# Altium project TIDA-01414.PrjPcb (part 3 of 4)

## Sheet TIDA-01414_SubWooferChannel.SchDoc: Main Schematic
size 431 x 279 mm; Date: Not shown in title block; ApprovedBy: Not shown in title block; CheckedBy: Not shown in title block; Author: Not shown in title block; CompanyName: Not shown in title block; DrawnBy: LDN; Engineer: Not shown in title block; Organization: Not shown in title block; Address1: Not shown in title block; Address2: Not shown in title block; Address3: Not shown in title block; Address4: Not shown in title block; DocumentNumber: 8; Revision: Use project parameter SCH_Rev; SheetNumber: 8; SheetTotal: 12; PageSetup: Record=PageOptions¦CenterHorizontal=True¦CenterVertical=True¦PrintScale=1.00¦XCorrection=1.00¦YCorrection=1.00¦PrintKind=0¦BorderSize=5000000¦LeftOffset=0¦BottomOffset=0¦Orientation=2¦PaperLength=1000¦PaperWidth=1000¦Scale=100¦PaperSource=15¦PrintQuality=600¦MediaType=1¦DitherType=10¦PaperKind=Letter¦PrintScaleMode=1
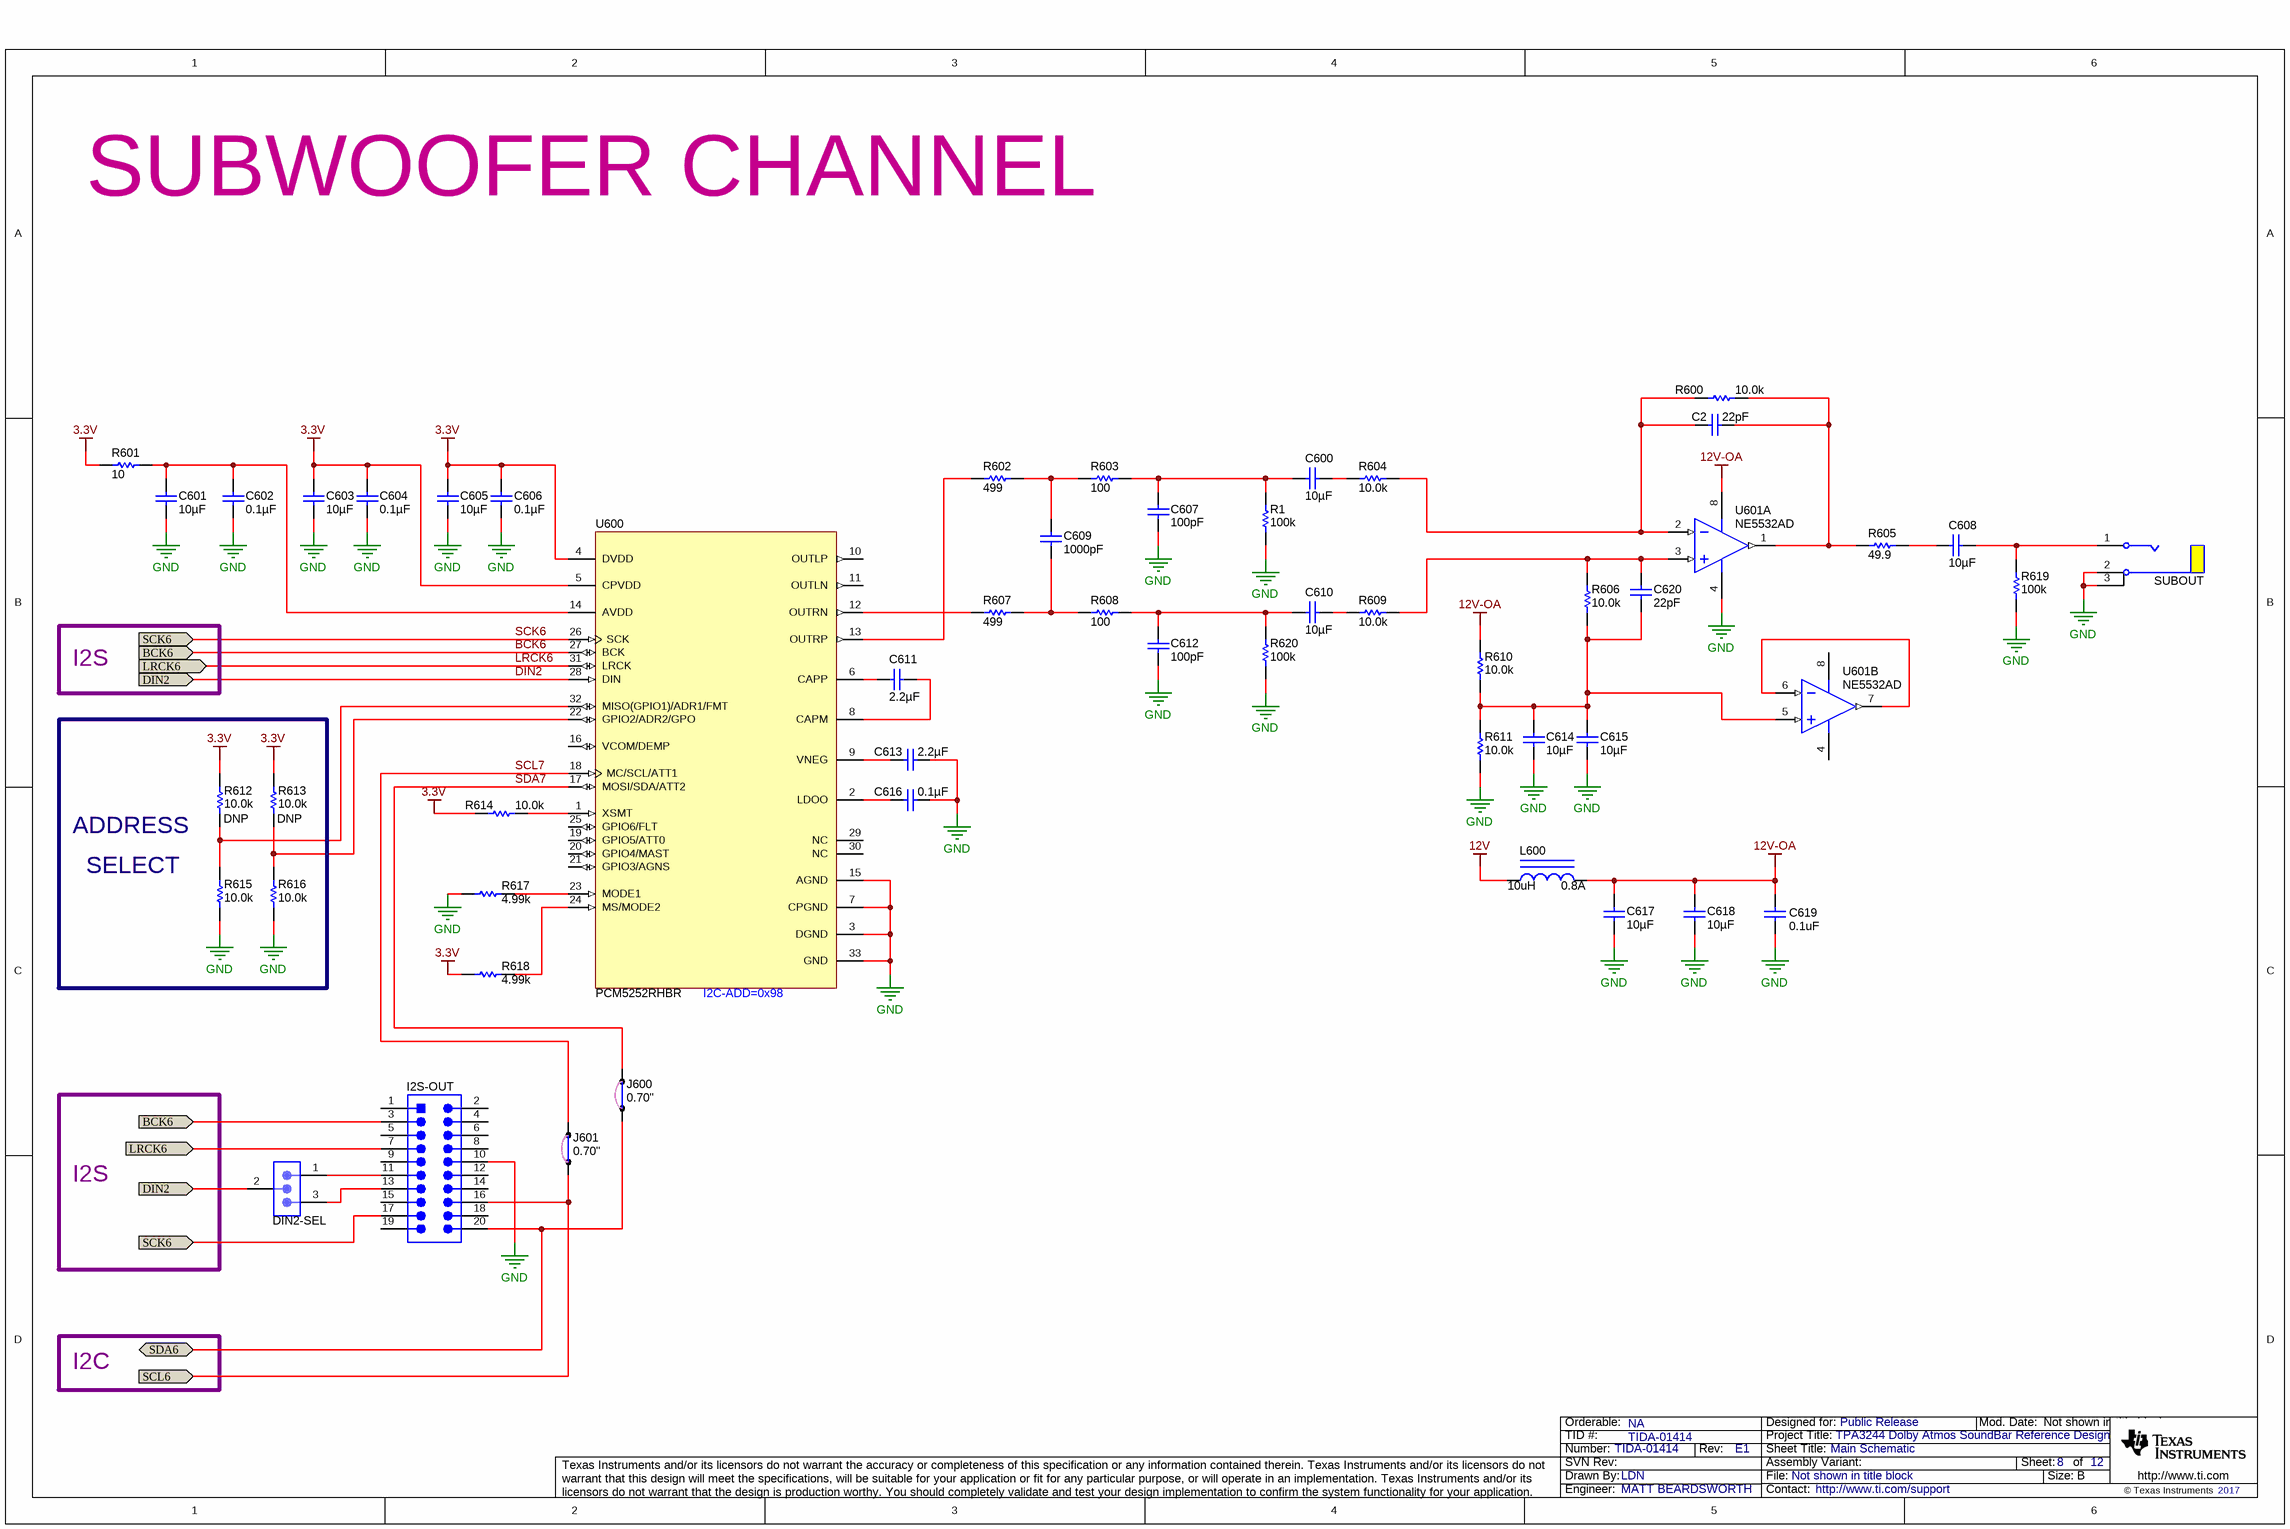
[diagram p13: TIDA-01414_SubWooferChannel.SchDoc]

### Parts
C2  ValueDisplayed: 22pF  [0603L]  (hidden comment: GRM1885C1H220JA01D)
C600  ValueDisplayed: 10µF  [1206_180]  (hidden comment: GRM31CR71C106KAC7L)
C601  ValueDisplayed: 10µF  [0603L]  (hidden comment: GRM188R61A106ME69D)
C602  ValueDisplayed: 0.1µF  [0402L]  (hidden comment: GRM155R71A104KA01D)
C603  ValueDisplayed: 10µF  [0603L]  (hidden comment: GRM188R61A106ME69D)
C604  ValueDisplayed: 0.1µF  [0402L]  (hidden comment: GRM155R71A104KA01D)
C605  ValueDisplayed: 10µF  [0603L]  (hidden comment: GRM188R61A106ME69D)
C606  ValueDisplayed: 0.1µF  [0402L]  (hidden comment: GRM155R71A104KA01D)
C607  ValueDisplayed: 100pF  [0603L]  (hidden comment: GRM1885C1H101JA01D)
C608  ValueDisplayed: 10µF  [0603L]  (hidden comment: GRM188R61C106MAALD)
C609  ValueDisplayed: 1000pF  [0402L]  (hidden comment: GRM1555C1H102JA01D)
C610  ValueDisplayed: 10µF  [1206_180]  (hidden comment: GRM31CR71C106KAC7L)
C611  ValueDisplayed: 2.2µF  [0402L]  (hidden comment: C1005X5R1A225K050BC)
C612  ValueDisplayed: 100pF  [0603L]  (hidden comment: GRM1885C1H101JA01D)
C613  ValueDisplayed: 2.2µF  [0402L]  (hidden comment: C1005X5R1A225K050BC)
C614  ValueDisplayed: 10µF  [0603L]  (hidden comment: GRM188R61C106MAALD)
C615  ValueDisplayed: 10µF  [0603L]  (hidden comment: GRM188R61C106MAALD)
C616  ValueDisplayed: 0.1µF  [0402L]  (hidden comment: GRM155R71A104KA01D)
C617  ValueDisplayed: 10µF  [0805_KTR]  (hidden comment: EMK212BJ106KG-T)
C618  ValueDisplayed: 10µF  [0805_KTR]  (hidden comment: EMK212BJ106KG-T)
C619  value 0.1uF  [0603L]  (hidden comment: C0603C104K5RACTU)
C620  ValueDisplayed: 22pF  [0603L]  (hidden comment: GRM1885C1H220JA01D)
DIN2-SEL  (no value)  [PBC03SAAN]
I2S-OUT  SBH11-PBPC-D10-ST-BK  [Sullins_SBH11-xxxC-D10-ST]  (value not drawn)
J600  0.70"  [CONN_923345-07-C]
J601  0.70"  [CONN_923345-07-C]
L600  value 10uH  Value2: 0.8A  [NRS4012]  (hidden comment: NRS4012T100MDGJV)
R1  value 100k  [0402L]  (hidden comment: CRCW0402100KFKED)
R600  ValueDisplayed: 10.0k  [0402L]  (hidden comment: ERJ-2RKF1002X)
R601  ValueDisplayed: 10  [0603L]  (hidden comment: CRCW060310R0JNEA)
R602  ValueDisplayed: 499  [0603L]  (hidden comment: CRCW0603499RFKEA)
R603  ValueDisplayed: 100  [0603L]  (hidden comment: CRCW0603100RFKEA)
R604  ValueDisplayed: 10.0k  [0402L]  (hidden comment: ERJ-2RKF1002X)
R605  ValueDisplayed: 49.9  [0603L]  (hidden comment: CRCW060349R9FKEA)
R606  ValueDisplayed: 10.0k  [0402L]  (hidden comment: ERJ-2RKF1002X)
R607  ValueDisplayed: 499  [0603L]  (hidden comment: CRCW0603499RFKEA)
R608  ValueDisplayed: 100  [0603L]  (hidden comment: CRCW0603100RFKEA)
R609  ValueDisplayed: 10.0k  [0402L]  (hidden comment: ERJ-2RKF1002X)
R610  ValueDisplayed: 10.0k  [0402L]  (hidden comment: ERJ-2RKF1002X)
R611  ValueDisplayed: 10.0k  [0402L]  (hidden comment: ERJ-2RKF1002X)
R612  DNP  ValueDisplayed: 10.0k  [0402L]
R613  DNP  ValueDisplayed: 10.0k  [0402L]
R614  ValueDisplayed: 10.0k  [0402L]  (hidden comment: ERJ-2RKF1002X)
R615  ValueDisplayed: 10.0k  [0402L]  (hidden comment: ERJ-2RKF1002X)
R616  ValueDisplayed: 10.0k  [0402L]  (hidden comment: ERJ-2RKF1002X)
R617  ValueDisplayed: 4.99k  [0402L]  (hidden comment: CRCW04024K99FKED)
R618  ValueDisplayed: 4.99k  [0402L]  (hidden comment: CRCW04024K99FKED)
R619  value 100k  [0402L]  (hidden comment: CRCW0402100KFKED)
R620  value 100k  [0402L]  (hidden comment: CRCW0402100KFKED)
SUBOUT  RCJ-024  [CONN_RCJ-024]  (value not drawn)
U600  PCM5252RHBR  [RHB0032E]
U601  NE5532AD  [D0008A_N]  (parts A,B of 2)

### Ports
BCK6 (in), DIN2 (in), LRCK6 (in), SCK6 (in), SCL6 (in), SDA6 (bidir)

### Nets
3.3V: C603.1 C604.1 C605.1 C606.1 R601.1 R612.2 R613.2 R614.1 R618.2 U600.4(DVDD) U600.5(CPVDD)
12V: L600.1
12V-OA: C617.1 C618.1 C619.1 L600.2 R610.1 U601.8(VCC+)
GND: C601.2 C602.2 C603.2 C604.2 C605.2 C606.2 C607.2 C612.2 C613.2 C614.1 C615.1 C616.2 C617.2 C618.2 C619.2 I2S-OUT.10 R1.1 R611.2 R615.1 R616.1 R617.2 R619.1 R620.1 SUBOUT.2 SUBOUT.3(R) U600.3(DGND) U600.7(CPGND) U600.15(AGND) U600.33(GND) U601.4(VCC-)
BCK6: I2S-OUT.3 U600.27(BCK) ; port BCK6
DIN2: DIN2-SEL.2 U600.28(DIN) ; port DIN2
LRCK6: I2S-OUT.7 U600.31(LRCK) ; port LRCK6
SCK6: I2S-OUT.17 U600.26(SCK) ; port SCK6
SCL6: I2S-OUT.16 J601.1 ; port SCL6
SCL7: J601.2 U600.18(MC/SCL/ATT1)
SDA6: I2S-OUT.20 J600.1 ; port SDA6
SDA7: J600.2 U600.17(MOSI/SDA/ATT2)
NetC2_1: C2.1 R600.2 R604.1 U601.2(IN1-)
NetC2_2: C2.2 R600.1 R605.1 U601.1(OUT1)
NetC600_1: C600.1 C607.1 R1.2 R603.2
NetC600_2: C600.2 R604.2
NetC601_1: C601.1 C602.1 R601.2 U600.14(AVDD)
NetC608_1: C608.1 R619.2 SUBOUT.1
NetC608_2: C608.2 R605.2
NetC609_1: C609.1 R602.2 R603.1
NetC609_2: C609.2 R607.2 R608.1
NetC610_1: C610.1 C612.1 R608.2 R620.2
NetC610_2: C610.2 R609.2
NetC611_1: C611.1 U600.6(CAPP)
NetC611_2: C611.2 U600.8(CAPM)
NetC613_1: C613.1 U600.9(VNEG)
NetC614_2: C614.2 C615.2 C620.1 R606.2 R610.2 R611.1 U601.5(IN2+)
NetC616_1: C616.1 U600.2(LDOO)
NetC620_2: C620.2 R606.1 R609.1 U601.3(IN1+)
NetDIN2-SEL_1: DIN2-SEL.1 I2S-OUT.11
NetDIN2-SEL_3: DIN2-SEL.3 I2S-OUT.13
NetR602_1: R602.1 U600.13(OUTRP)
NetR607_1: R607.1 U600.12(OUTRN)
NetR612_1: R612.1 R615.2 U600.32(MISO(GPIO1)/ADR1/FMT)
NetR613_1: R613.1 R616.2 U600.22(GPIO2/ADR2/GPO)
NetR614_2: R614.2 U600.1(XSMT)
NetR617_1: R617.1 U600.23(MODE1)
NetR618_1: R618.1 U600.24(MS/MODE2)
NetU601_6: U601.6(IN2-) U601.7(OUT2)

Not connected (* = marked no-connect by the designer): I2S-OUT 1 2 4 5 6 8 9 12 14 15 18 19; U600 10(OUTLP) 11(OUTLN) 16(VCOM/DEMP) 19(GPIO5/ATT0) 20(GPIO4/MAST) 21(GPIO3/AGNS) 25(GPIO6/FLT) 29(NC) 30(NC)

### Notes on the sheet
- SUBWOOFER CHANNEL
- I2S
- ADDRESS
- SELECT
- (near U600) I2C-ADD=0x98
- I2C

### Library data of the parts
C2 C620 = GRM1885C1H220JA01D: CAP, CERM, 22 pF, 50 V, +/- 5%, C0G/NP0, 0603; Manufacturer: MuRata; Polarized: N; CompType: Capacitor; Value: 22pF; U/M: EA; Cap_F: 0.000000000022; Tolerance_%: 5; Value1: Unknown; VDC_V: 50; Value2: 50V; TaMin_C: -55; TaMax_C: 125; Cap_Case: 0603; AEC Category: Q200; SizeArea_mm2: 1.28; SizeAreaWB_mm2: 4.68; SizeX_mm: 1.6; SizeY_mm: 0.8; SizeZ_mm: 1
C600 C610 = GRM31CR71C106KAC7L: CAP, CERM, 10 µF, 16 V, +/- 10%, X7R, 1206; Manufacturer: MuRata; Polarized: N; CompType: Capacitor; Value: 10uF; U/M: EA; Cap_F: 0.00001; Tolerance_%: 10; Value1: Unknown; VDC_V: 16; Value2: 16V; TaMin_C: -55; TaMax_C: 125; Cap_Case: 1206; AEC Category: Q200; SizeArea_mm2: 5.12; SizeAreaWB_mm2: 10.92; SizeX_mm: 3.2; SizeY_mm: 1.6; SizeZ_mm: 1.8
C601 C603 C605 = GRM188R61A106ME69D: CAP, CERM, 10 µF, 10 V, +/- 20%, X5R, 0603; Manufacturer: MuRata; Polarized: N; CompType: Capacitor; Value: 10uF; U/M: EA; Cap_F: 0.00001; Tolerance_%: 20; Value1: Unknown; VDC_V: 10; Value2: 10V; TaMin_C: -55; TaMax_C: 85; Cap_Case: 0603; AEC Category: Q200
C602 C604 C606 C616 = GRM155R71A104KA01D: CAP, CERM, 0.1 µF, 10 V, +/- 10%, X7R, 0402; Manufacturer: MuRata; Polarized: N; CompType: Capacitor; Value: 0.1uF; U/M: EA; Cap_F: 0.0000001; Tolerance_%: 10; Value1: Unknown; Value2: 10V; TaMin_C: -55; TaMax_C: 125; Cap_Case: 0402; AEC Category: Q200
C607 C612 = GRM1885C1H101JA01D: CAP, CERM, 100 pF, 50 V, +/- 5%, C0G/NP0, 0603; Manufacturer: MuRata; Polarized: N; CompType: Capacitor; Value: 100pF; U/M: EA; Cap_F: 0.0000000001; Tolerance_%: 5; Value1: Unknown; VDC_V: 50; Value2: 50V; TaMin_C: -55; TaMax_C: 125; Cap_Case: 0603; AEC Category: Q200
C608 C614 C615 = GRM188R61C106MAALD: CAP, CERM, 10 µF, 16 V, +/- 20%, X5R, 0603; Manufacturer: MuRata; Polarized: N; CompType: Capacitor; Value: 10uF; U/M: EA; Cap_F: 0.00001; Tolerance_%: 20; Value1: Unknown; VDC_V: 16; Value2: 16V; TaMin_C: -55; TaMax_C: 85; Cap_Case: 0603; AEC Category: Q200; SizeArea_mm2: 1.28; SizeAreaWB_mm2: 4.68; SizeX_mm: 1.6; SizeY_mm: 0.8; SizeZ_mm: 1
C609 = GRM1555C1H102JA01D: CAP, CERM, 1000 pF, 50 V, +/- 5%, C0G/NP0, 0402; Manufacturer: MuRata; Polarized: N; CompType: Capacitor; Value: 1000pF; U/M: EA; Cap_F: 0.000000001; Tolerance_%: 5; Value1: Unknown; VDC_V: 50; Value2: 50V; TaMin_C: -55; TaMax_C: 125; Cap_Case: 0402; AEC Category: Q200
C611 C613 = C1005X5R1A225K050BC: CAP, CERM, 2.2 µF, 10 V, +/- 10%, X5R, 0402; Manufacturer: TDK; Polarized: N; CompType: Capacitor; Value: 2.2uF; U/M: EA; Cap_F: 0.0000022; Tolerance_%: 10; Value1: Unknown; Value2: 10V; TaMin_C: -55; TaMax_C: 85; Cap_Case: 0402; AEC Category: Q200
C617 C618 = EMK212BJ106KG-T: CAP, CERM, 10 µF, 16 V, +/- 10%, X5R, 0805; Manufacturer: Taiyo Yuden; Polarized: N; CompType: Capacitor; Value: 10uF; U/M: EA; Cap_F: 0.00001; Tolerance_%: 10; Value1: Unknown; VDC_V: 16; Value2: 16V; TaMin_C: -55; TaMax_C: 85; Cap_Case: 0805; AEC Category: Q200
C619 = C0603C104K5RACTU: CAP, CERM, 0.1 µF, 50 V, +/- 10%, X7R, 0603; Manufacturer: Kemet; Polarized: N; CompType: Capacitor; ValueDisplayed: 0.1µF; U/M: EA; Cap_F: 0.0000001; Tolerance_%: 10; Value1: Unknown; VDC_V: 50; Value2: 50V; TaMin_C: -55; TaMax_C: 125; Cap_Case: 0603; AEC Category: Q200
DIN2-SEL = SIP3-90_PBC03SAAN: Header, 100mil, 3x1, Gold, TH; Manufacturer: Sullins Connector Solutions; Value: 1x3; U/M: EA
I2S-OUT = SBH11-PBPC-D10-ST-BK: Header (Shrouded), 2.54mm, 10x2, Gold, Black, TH; Manufacturer: Sullins Connector Solutions; SymbolCreator: a0412235; Pitch_mm: 2.54; Gender: Male; Shrouded: Y; Row_Count: 2; Current_A: 3; Voltage_V: 1000
J600 J601 = 923345-07-C: Jumper Wire, 700mil spacing, Violet, pkg of 150, TH; Manufacturer: 3M; SymbolCreator: a0412235
L600 = NRS4012T100MDGJV: Inductor, Wirewound, 10 µH, 0.8 A, 0.204 ohm, SMD; Manufacturer: Taiyo Yuden; ValueDisplayed: 10µH; Ind_H: 10.0E-6; Imax_A: 0.8; Irms: 1.1A @ 40C rise; Isat: 0.8A @ 30% inductance drop; DCR_ohm: 0.204; AEC Category: Q200
R1 R619 R620 = CRCW0402100KFKED: RES, 100 k, 1%, 0.063 W, 0402; Manufacturer: Vishay-Dale; CompType: Resistor; Res_ohm: 100000; Tolerance_%: 1; Power_W: 0.063; Value2: 0.063W; VDC_V: 50; TempCo: 100 ppm/C; EIA_Code: E96; U/M: EA; AEC Category: Q200
R600 R604 R606 R609-R616 = ERJ-2RKF1002X: RES, 10.0 k, 1%, 0.1 W, 0402; Manufacturer: Panasonic; CompType: Resistor; Value: 10.0k; Res_ohm: 10000; Value_Code: 10k0; Tolerance_%: 1; Power_W: 0.1; Value2: 0.1W; VDC_V: 50; TempCo: 100 ppm/C; EIA_Code: E96; U/M: EA; AEC Category: Q200
R601 = CRCW060310R0JNEA: RES, 10, 5%, 0.1 W, 0603; Manufacturer: Vishay-Dale; CompType: Resistor; Value: 10; Value_Code: 10R0; Tolerance_%: 5; Power_W: 0.1; Value2: 0.1W; VDC_V: 75; TempCo: 200 ppm/C; EIA_Code: E24; U/M: EA; AEC Category: Q200
R602 R607 = CRCW0603499RFKEA: RES, 499, 1%, 0.1 W, 0603; Manufacturer: Vishay-Dale; CompType: Resistor; Value: 499; Value_Code: 499R; Tolerance_%: 1; Power_W: 0.1; Value2: 0.1W; VDC_V: 75; TempCo: 100 ppm/C; EIA_Code: E96; U/M: EA; AEC Category: Q200
R603 R608 = CRCW0603100RFKEA: RES, 100, 1%, 0.1 W, 0603; Manufacturer: Vishay-Dale; CompType: Resistor; Value: 100; Value_Code: 100R; Tolerance_%: 1; Power_W: 0.1; Value2: 0.1W; VDC_V: 75; TempCo: 100 ppm/C; EIA_Code: E96; U/M: EA; AEC Category: Q200
R605 = CRCW060349R9FKEA: RES, 49.9, 1%, 0.1 W, 0603; Manufacturer: Vishay-Dale; CompType: Resistor; Value: 49.9; Value_Code: 49R9; Tolerance_%: 1; Power_W: 0.1; Value2: 0.1W; VDC_V: 75; TempCo: 100 ppm/C; EIA_Code: E96; U/M: EA; AEC Category: Q200; SizeArea_mm2: 1.28; SizeX_mm: 1.6; SizeY_mm: 0.8
R617 R618 = CRCW04024K99FKED: RES, 4.99 k, 1%, 0.063 W, 0402; Manufacturer: Vishay-Dale; CompType: Resistor; Value: 4.99k; Res_ohm: 4990; Value_Code: 4k99; Tolerance_%: 1; Power_W: 0.063; Value2: 0.063W; VDC_V: 50; TempCo: 100 ppm/C; EIA_Code: E96; U/M: EA; AEC Category: Q200
SUBOUT = RCJ-024: RCA Jack, Vertical, Yellow, TH; Manufacturer: CUI Inc.; SymbolCreator: Altium; Gender: Female; ContactFinish: Tin; Voltage_V: 500
U600 = PCM5252RHBR: 4.2VRMS DirectPath™, 114dB Audio Stereo Differential-Output DAC with 32-bit, 384kHz PCM Interface, RHB0032E; Alternate PartNumber: PCM5252RHBT; Manufacturer: Texas Instruments; SymbolCreator: Altium; CompType: IC; U/M: EA
U601 = NE5532AD: Dual Low-Noise Operational Amplifier, 10 to 30 V, 0 to 70 degC, 8-pin SOIC (D0008A), Green (RoHS & no Sb/Br); Alternate Manufacturer: Texas Instruments; Alternate PartNumber: Equivalent; CMRR(Min)(dB): 70; GBW(Typ)(MHz): 10; IIB(Max)(pA): 800000; Iq per channel(Max)(mA): 4; Number of Channels: 2; Slew Rate(Typ)(V/us): 9; Sub Family: General Purpose Amplifier, High Supply Voltage Amplifier (>=30V), Low Noise Amp (<=10nV/rtHz); Total Supply Voltage(Max)(+5V is 5, +/-5V is 10): 30; Vn at 1kHz(Typ)(nV/rtHz): 5

## Sheet TIDA-01414_PowerSupplies.SchDoc: Hardware
size 323 x 209 mm; Date: Not shown in title block; ApprovedBy: Not shown in title block; CheckedBy: Not shown in title block; Author: Not shown in title block; CompanyName: Not shown in title block; DrawnBy: LDN; Engineer: Not shown in title block; Organization: Not shown in title block; Address1: Not shown in title block; Address2: Not shown in title block; Address3: Not shown in title block; Address4: Not shown in title block; DocumentNumber: 9; Revision: Use project parameter SCH_Rev; SheetNumber: 9; SheetTotal: 12; PageSetup: Record=PageOptions¦CenterHorizontal=True¦CenterVertical=True¦PrintScale=1.00¦XCorrection=1.00¦YCorrection=1.00¦PrintKind=0¦BorderSize=5000000¦LeftOffset=0¦BottomOffset=0¦Orientation=2¦PaperLength=1000¦PaperWidth=1000¦Scale=100¦PaperSource=15¦PrintQuality=600¦MediaType=1¦DitherType=10¦PaperKind=Letter¦PrintScaleMode=1
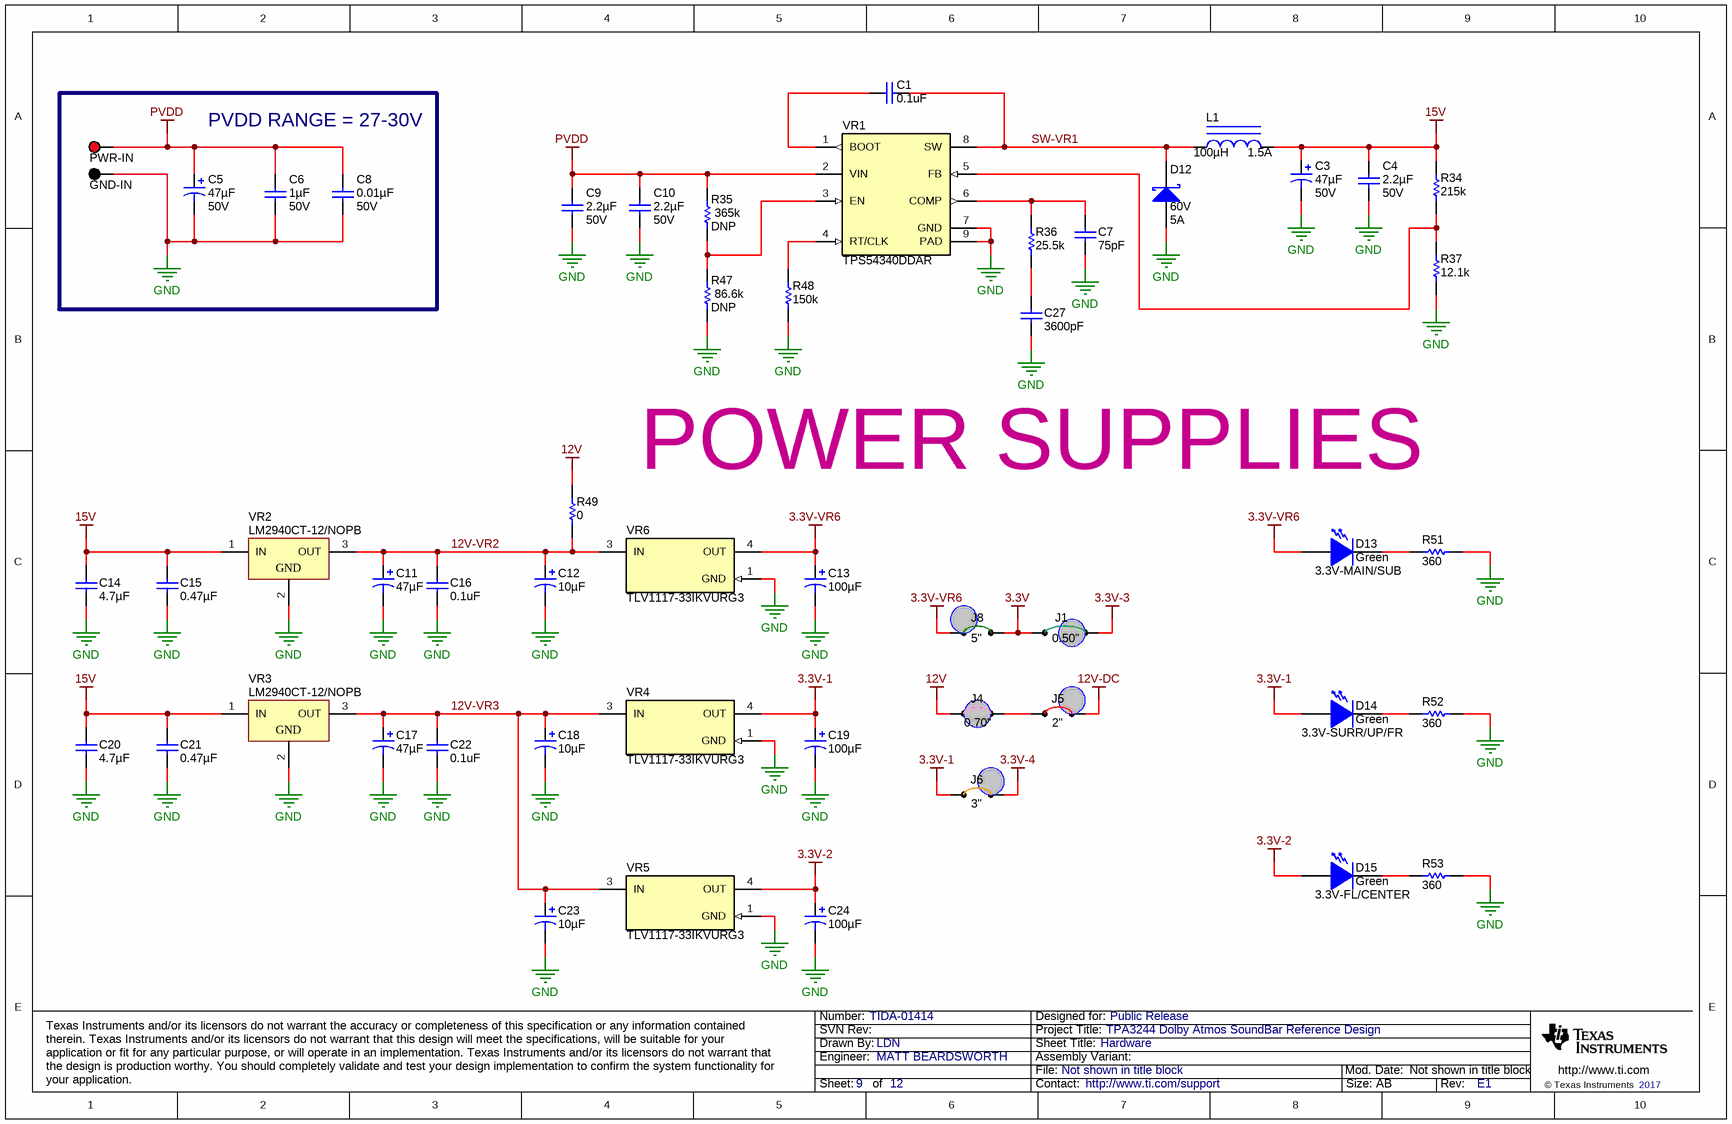
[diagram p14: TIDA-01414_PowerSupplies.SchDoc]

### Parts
C1  value 0.1uF  [0603L]  (hidden comment: C0603C104K5RACTU)
C3  ValueDisplayed: 47µF  Value2: 50V  [SM_RADIAL_E]  (hidden comment: +)
C4  ValueDisplayed: 2.2µF  Value2: 50V  [0805_KTR]  (hidden comment: C2012X7R1H225K125AC)
C5  ValueDisplayed: 47µF  Value2: 50V  [SM_RADIAL_E]  (hidden comment: +)
C6  ValueDisplayed: 1µF  Value2: 50V  [0603L]  (hidden comment: UMK107AB7105KA-T)
C7  ValueDisplayed: 75pF  [0603L]  (hidden comment: GRM1885C1H750JA01D)
C8  ValueDisplayed: 0.01µF  Value2: 50V  [0603L]  (hidden comment: C0603C103K5RACTU)
C9  ValueDisplayed: 2.2µF  Value2: 50V  [0805_KTR]  (hidden comment: C2012X7R1H225K125AC)
C10  ValueDisplayed: 2.2µF  Value2: 50V  [0805_KTR]  (hidden comment: C2012X7R1H225K125AC)
C11  ValueDisplayed: 47µF  [SM_RADIAL_D]  (hidden comment: +)
C12  ValueDisplayed: 10µF  [SM_RADIAL_B]  (hidden comment: +)
C13  ValueDisplayed: 100µF  [SM_RADIAL_C]  (hidden comment: +)
C14  ValueDisplayed: 4.7µF  [1206_180L]  (hidden comment: GRM31CR71E475KA88L)
C15  ValueDisplayed: 0.47µF  [0603L]  (hidden comment: GRM188R71E474KA12D)
C16  value 0.1uF  [0603L]  (hidden comment: C0603C104K5RACTU)
C17  ValueDisplayed: 47µF  [SM_RADIAL_D]  (hidden comment: +)
C18  ValueDisplayed: 10µF  [SM_RADIAL_B]  (hidden comment: +)
C19  ValueDisplayed: 100µF  [SM_RADIAL_C]  (hidden comment: +)
C20  ValueDisplayed: 4.7µF  [1206_180L]  (hidden comment: GRM31CR71E475KA88L)
C21  ValueDisplayed: 0.47µF  [0603L]  (hidden comment: GRM188R71E474KA12D)
C22  value 0.1uF  [0603L]  (hidden comment: C0603C104K5RACTU)
C23  ValueDisplayed: 10µF  [SM_RADIAL_B]  (hidden comment: +)
C24  ValueDisplayed: 100µF  [SM_RADIAL_C]  (hidden comment: +)
C27  ValueDisplayed: 3600pF  [0603L]  (hidden comment: GRM1885C1H362JA01D)
D12  value 60V  Value1: 5A  [SMC]  (hidden comment: B560C-13-F)
D13  3.3V-MAIN/SUB  value Green  [LED_LTST-C171]
D14  3.3V-SURR/UP/FR  value Green  [LED_LTST-C171]
D15  3.3V-FL/CENTER  value Green  [LED_LTST-C171]
GND-IN  DNP  [Keystone5001]  (value not drawn)
J1  0.50"  [WireJumper_923345-05-C]
J4  0.70"  [CONN_923345-07-C]
J5  2"  [3M_923345-20-C]
J6  3"  [3M_923345-30-C]
J8  5"  [3M_923345-50-C]
L1  ValueDisplayed: 100µH  Value2: 1.5A  [WE-PD_1050]  (hidden comment: 7447714101)
PWR-IN  DNP  [Keystone5000]  (value not drawn)
R34  ValueDisplayed: 215k  [0603L]  (hidden comment: CRCW0603215KFKEA)
R35  DNP  ValueDisplayed: 365k  [0603L]
R36  ValueDisplayed: 25.5k  [0603L]  (hidden comment: CRCW060325K5FKEA)
R37  ValueDisplayed: 12.1k  [0603L]  (hidden comment: CRCW060312K1FKEA)
R47  DNP  ValueDisplayed: 86.6k  [0603L]
R48  ValueDisplayed: 150k  [0603L]  (hidden comment: RC0603FR-07150KL)
R49  ValueDisplayed: 0  [1206L]  (hidden comment: CRCW12060000Z0EA)
R51  value 360  [0402L]  (hidden comment: CRCW0402360RJNED)
R52  value 360  [0402L]  (hidden comment: CRCW0402360RJNED)
R53  value 360  [0402L]  (hidden comment: CRCW0402360RJNED)
VR1  TPS54340DDAR  [DDA0008E_N]
VR2  LM2940CT-12/NOPB  [TO-220AB_Horizontal_100mil]
VR3  LM2940CT-12/NOPB  [TO-220AB_Horizontal_100mil]
VR4  TLV1117-33IKVURG3  [KVU0003A_N]
VR5  TLV1117-33IKVURG3  [KVU0003A_N]
VR6  TLV1117-33IKVURG3  [KVU0003A_N]

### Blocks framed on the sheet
PVDD RANGE = 27-30V: C5 C6 C8 GND-IN PWR-IN

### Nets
3.3V: J1.1 J8.1
3.3V-1: C19.1(+) D14.1(A) J6.1 VR4.4(OUT)
3.3V-2: C24.1(+) D15.1(A) VR5.4(OUT)
3.3V-3: J1.2
3.3V-4: J6.2
3.3V-VR6: C13.1(+) D13.1(A) J8.2 VR6.4(OUT)
12V: J4.1 R49.1
12V-DC: J5.2
15V: C3.1(+) C4.1 C14.1 C15.1 C20.1 C21.1 L1.2 R34.2 VR2.1(IN) VR3.1(IN)
GND: C3.2(-) C4.2 C5.2(-) C6.1 C7.2 C8.2 C9.2 C10.2 C11.2(-) C12.2(-) C13.2(-) C14.2 C15.2 C16.1 C17.2(-) C18.2(-) C19.2(-) C20.2 C21.2 C22.1 C23.2(-) C24.2(-) C27.2 D12.2(A) GND-IN.1 R37.1 R47.1 R48.1 R51.2 R52.2 R53.2 VR1.7(GND) VR1.9(PAD) VR2.2(GND) VR3.2(GND) VR4.1(GND) VR5.1(GND) VR6.1(GND)
PVDD: C5.1(+) C6.2 C8.1 C9.1 C10.1 PWR-IN.1 R35.2 VR1.2(VIN)
12V-VR2: C11.1(+) C12.1(+) C16.2 R49.2 VR2.3(OUT) VR6.3(IN)
12V-VR3: C17.1(+) C18.1(+) C22.2 C23.1(+) VR3.3(OUT) VR4.3(IN) VR5.3(IN)
SW-VR1: C1.2 D12.1(K) L1.1 VR1.8(SW)
NetC1_1: C1.1 VR1.1(BOOT)
NetC7_1: C7.1 R36.2 VR1.6(COMP)
NetC27_1: C27.1 R36.1
NetD13_2: D13.2(K) R51.1
NetD14_2: D14.2(K) R52.1
NetD15_2: D15.2(K) R53.1
NetJ4_2: J4.2 J5.1
NetR34_1: R34.1 R37.2 VR1.5(FB)
NetR35_1: R35.1 R47.2 VR1.3(EN)
NetR48_2: R48.2 VR1.4(RT/CLK)

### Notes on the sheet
- POWER SUPPLIES

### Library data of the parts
C1 C16 C22 = C0603C104K5RACTU: as C619 on sheet TIDA-01414_SubWooferChannel
C3 C5 = EEE-FK1H470P: CAP, AL, 47 µF, 50 V, +/- 20%, 0.68 ohm, SMD; Manufacturer: Panasonic; Polarized: Y; CompType: Capacitor; Value: 47uF; U/M: EA; Cap_F: 0.000047; Tolerance_%: 20; VDC_V: 50; ESR_ohm: 0.68; IRMS_A: 0.195; TaMin_C: -55; TaMax_C: 105; Cap_Case: E; AEC Category: Q200
C4 C9 C10 = C2012X7R1H225K125AC: CAP, CERM, 2.2 µF, 50 V, +/- 10%, X7R, 0805; Manufacturer: TDK; Polarized: N; CompType: Capacitor; Value: 2.2uF; U/M: EA; Cap_F: 0.0000022; Tolerance_%: 10; Value1: Unknown; VDC_V: 50; TaMin_C: -55; TaMax_C: 125; Cap_Case: 0805; AEC Category: Q200
C6 = UMK107AB7105KA-T: CAP, CERM, 1 µF, 50 V, +/- 10%, X7R, 0603; Manufacturer: Taiyo Yuden; Polarized: N; CompType: Capacitor; Value: 1uF; U/M: EA; Cap_F: 0.000001; Tolerance_%: 10; Value1: Unknown; VDC_V: 50; TaMin_C: -55; TaMax_C: 125; Cap_Case: 0603; AEC Category: Q200
C7 = GRM1885C1H750JA01D: CAP, CERM, 75 pF, 50 V, +/- 5%, C0G/NP0, 0603; Manufacturer: MuRata; Polarized: N; CompType: Capacitor; Value: 75pF; U/M: EA; Cap_F: 0.000000000075; Tolerance_%: 5; Value1: Unknown; VDC_V: 50; Value2: 50V; TaMin_C: -55; TaMax_C: 125; Cap_Case: 0603; AEC Category: Q200; SizeArea_mm2: 1.28; SizeAreaWB_mm2: 4.68; SizeX_mm: 1.6; SizeY_mm: 0.8; SizeZ_mm: 1
C8 = C0603C103K5RACTU: CAP, CERM, 0.01 µF, 50 V, +/- 10%, X7R, 0603; Manufacturer: Kemet; Polarized: N; CompType: Capacitor; Value: 0.01uF; U/M: EA; Cap_F: 0.00000001; Tolerance_%: 10; Value1: Unknown; VDC_V: 50; TaMin_C: -55; TaMax_C: 125; Cap_Case: 0603; AEC Category: Q200
C11 C17 = EEE-FK1C470P: CAP, AL, 47 µF, 16 V, +/- 20%, 0.36 ohm, SMD; Manufacturer: Panasonic; Polarized: Y; CompType: Capacitor; Value: 47uF; U/M: EA; Cap_F: 0.000047; Tolerance_%: 20; VDC_V: 16; Value2: 16V; ESR_ohm: 0.36; IRMS_A: 0.24; TaMin_C: -55; TaMax_C: 105; Cap_Case: D; AEC Category: Q200
C12 C18 C23 = EEE-FK1C100R: CAP, AL, 10 µF, 16 V, +/- 20%, 1.35 ohm, SMD; Manufacturer: Panasonic; Polarized: Y; CompType: Capacitor; Value: 10uF; U/M: EA; Cap_F: 0.00001; Tolerance_%: 20; VDC_V: 16; Value2: 16V; ESR_ohm: 1.35; IRMS_A: 0.09; TaMin_C: -55; TaMax_C: 105; Cap_Case: B; AEC Category: Q200
C13 C19 C24 = EEE-FK0J101UR: CAP, AL, 100 µF, 6.3 V, +/- 20%, 0.7 ohm, SMD; Manufacturer: Panasonic; Polarized: Y; CompType: Capacitor; Value: 100uF; U/M: EA; Cap_F: 0.0001; Tolerance_%: 20; Value1: 0.7 ohm; VDC_V: 6.3; Value2: 6.3V; ESR_ohm: 0.7; IRMS_A: 0.16; TaMin_C: -55; TaMax_C: 105; Cap_Case: C; AEC Category: Q200
C14 C20 = GRM31CR71E475KA88L: CAP, CERM, 4.7 µF, 25 V, +/- 10%, X7R, 1206; Manufacturer: MuRata; Polarized: N; CompType: Capacitor; Value: 4.7uF; U/M: EA; Cap_F: 0.0000047; Tolerance_%: 10; Value1: Unknown; VDC_V: 25; Value2: 25V; TaMin_C: -55; TaMax_C: 125; Cap_Case: 1206; AEC Category: Q200
C15 C21 = GRM188R71E474KA12D: CAP, CERM, 0.47 µF, 25 V, +/- 10%, X7R, 0603; Manufacturer: MuRata; Polarized: N; CompType: Capacitor; Value: 0.47uF; U/M: EA; Cap_F: 0.00000047; Tolerance_%: 10; Value1: Unknown; VDC_V: 25; Value2: 25V; TaMin_C: -55; TaMax_C: 125; Cap_Case: 0603; AEC Category: Q200
C27 = GRM1885C1H362JA01D: CAP, CERM, 3600 pF, 50 V, +/- 5%, C0G/NP0, 0603; Manufacturer: MuRata; Polarized: N; CompType: Capacitor; Value: 3600pF; U/M: EA; Cap_F: 0.0000000036; Tolerance_%: 5; Value1: Unknown; VDC_V: 50; Value2: 50V; TaMin_C: -55; TaMax_C: 125; Cap_Case: 0603; AEC Category: Q200; SizeArea_mm2: 1.28; SizeAreaWB_mm2: 4.68; SizeX_mm: 1.6; SizeY_mm: 0.8; SizeZ_mm: 1
D12 = B560C-13-F: Diode, Schottky, 60 V, 5 A, SMC; Manufacturer: Diodes Inc.; U/M: EA; Vf_V: 0.7; Value2: 0.7V; Io_A: 5; Vr_V: 60; TJmax_C: 125; RJC_CperW: 10; AEC Category: Q101; SizeAreaWB_mm2: 83.2686; SizeArea_mm2: 50.5686; SizeX_mm: 8.13; SizeY_mm: 6.22; SizeZ_mm: 2.6
D13-D15 = LTST-C171GKT: LED, Green, SMD; Manufacturer: Lite-On; Type: AlInGaP; Vf_V: 2.1; Value2: 2.1V; Io_A: 20; Value1: W; U/M: EA
GND-IN = 5001: Test Point, Miniature, Black, TH; Manufacturer: Keystone; CompType: Test Point Loop; ContactFinish: Silver
J1 = 923345-05-C: Jumper Wire, 500mil spacing, Green, pkg of 200; Manufacturer: 3M; SymbolCreator: a0412235
J4 = 923345-07-C: as J600 on sheet TIDA-01414_SubWooferChannel
J5 = 923345-20-C: Jumper Wire, 2" spacing, Red, pkg of 100, TH; Manufacturer: 3M; SymbolCreator: a0411947; Pitch_mm: 50.8; Gender: Male; Row_Count: 1; ContactFinish: Tin
J6 = 923345-30-C: Jumper Wire, 3" spacing, Orange, pkg of 75, TH; Manufacturer: 3M; SymbolCreator: a0411947; Pitch_mm: 76.2; Gender: Male; Row_Count: 1; ContactFinish: Tin
J8 = 923345-50-C: Jumper Wire, 5" spacing, Green, pkg of 75, TH; Manufacturer: 3M; SymbolCreator: a0411947; Pitch_mm: 127; Gender: Male; Row_Count: 1; ContactFinish: Tin
L1 = 7447714101: Inductor, Shielded Drum Core, Ferrite, 100 µH, 1.5 A, 0.165 ohm, SMD; Manufacturer: Wurth Elektronik; Value: 100uH; Ind_H: 100.0E-6; Imax_A: 1.5; Irms: 1.5A @ 40C rise; Isat: 1.75A @ 10% inductance drop; DCR_ohm: 0.165; AEC Category: Q200; SizeAreaWB_mm2: 144; SizeArea_mm2: 100; SizeX_mm: 10; SizeZ_mm: 5
PWR-IN = 5000: Test Point, Miniature, Red, TH; Manufacturer: Keystone; CompType: Test Point Loop; ContactFinish: Silver
R34 = CRCW0603215KFKEA: RES, 215 k, 1%, 0.1 W, 0603; Manufacturer: Vishay-Dale; CompType: Resistor; Value: 215k; Res_ohm: 215000; Tolerance_%: 1; Power_W: 0.1; Value2: 0.1W; VDC_V: 75; TempCo: 100 ppm/C; EIA_Code: E96; U/M: EA; AEC Category: Q200; SizeArea_mm2: 1.28; SizeX_mm: 1.6; SizeY_mm: 0.8
R35 = CRCW0603365KFKEA: RES, 365 k, 1%, 0.1 W, 0603; Manufacturer: Vishay-Dale; CompType: Resistor; Value: 365k; Res_ohm: 365000; Tolerance_%: 1; Power_W: 0.1; Value2: 0.1W; VDC_V: 75; TempCo: 100 ppm/C; EIA_Code: E96; U/M: EA; AEC Category: Q200; SizeArea_mm2: 1.28; SizeX_mm: 1.6; SizeY_mm: 0.8
R36 = CRCW060325K5FKEA: RES, 25.5 k, 1%, 0.1 W, 0603; Manufacturer: Vishay-Dale; CompType: Resistor; Value: 25.5k; Res_ohm: 25500; Value_Code: 25k5; Tolerance_%: 1; Power_W: 0.1; Value2: 0.1W; VDC_V: 75; TempCo: 100 ppm/C; EIA_Code: E96; U/M: EA; AEC Category: Q200; SizeArea_mm2: 1.28; SizeX_mm: 1.6; SizeY_mm: 0.8
R37 = CRCW060312K1FKEA: RES, 12.1 k, 1%, 0.1 W, 0603; Manufacturer: Vishay-Dale; CompType: Resistor; Value: 12.1k; Res_ohm: 12100; Value_Code: 12k1; Tolerance_%: 1; Power_W: 0.1; Value2: 0.1W; VDC_V: 75; TempCo: 100 ppm/C; EIA_Code: E96; U/M: EA; AEC Category: Q200; SizeArea_mm2: 1.28; SizeX_mm: 1.6; SizeY_mm: 0.8
R47 = CRCW060386K6FKEA: RES, 86.6 k, 1%, 0.1 W, 0603; Manufacturer: Vishay-Dale; CompType: Resistor; Value: 86.6k; Res_ohm: 86600; Value_Code: 86k6; Tolerance_%: 1; Power_W: 0.1; Value2: 0.1W; VDC_V: 75; TempCo: 100 ppm/C; EIA_Code: E96; U/M: EA; AEC Category: Q200; SizeArea_mm2: 1.28; SizeX_mm: 1.6; SizeY_mm: 0.8
R48 = RC0603FR-07150KL: RES, 150 k, 1%, 0.1 W, 0603; Manufacturer: Yageo America; CompType: Resistor; Value: 150k; Res_ohm: 150000; Tolerance_%: 1; Power_W: 0.1; Value2: 0.1W; VDC_V: 150; TempCo: 200 ppm/C; EIA_Code: E96; U/M: EA; AEC Category: Q200; SizeArea_mm2: 1.28; SizeX_mm: 1.6; SizeY_mm: 0.8
R49 = CRCW12060000Z0EA: RES, 0, 5%, 0.25 W, 1206; Manufacturer: Vishay-Dale; CompType: Resistor; Value: 0; Value_Code: 0000; Tolerance_%: 5; Power_W: 0.25; Value2: 0.25W; VDC_V: 200; TempCo: 200 ppm/C; EIA_Code: E24; U/M: EA; AEC Category: Q200; SizeArea_mm2: 5.12; SizeX_mm: 3.2; SizeY_mm: 1.6; SizeZ_mm: 1.35
R51-R53 = CRCW0402360RJNED: RES, 360, 5%, 0.063 W, 0402; Manufacturer: Vishay-Dale; CompType: Resistor; Value_Code: 360R; Tolerance_%: 5; Power_W: 0.063; Value2: 0.063W; VDC_V: 50; TempCo: 200 ppm/C; EIA_Code: E24; U/M: EA; AEC Category: Q200
VR1 = TPS54340DDAR: 42 V Input, 3.5 A, Step Down DC-DC Converter with Eco-mode, DDA0008E (SOIC-8); Manufacturer: Texas Instruments; SymbolCreator: a0411947; SizeArea_mm2: 31; SizeAreaWB_mm2: 57.4; SizeX_mm: 5; SizeY_mm: 6.2; SizeZ_mm: 1.7; CompType: IC; U/M: EA
VR2 VR3 = LM2940CT-12/NOPB: 1A Low Dropout Regulator, 3-pin TO-220, Pb-Free; Manufacturer: Texas Instruments; PackageTopMarking: NSUZXYTTE#*LM2940CT*-12 P+; PowerWise: N; CompType: LDO IC
VR4-VR6 = TLV1117-33IKVURG3: FIXED LOW-DROPOUT VOLTAGE REGULATOR, KVU0003A (TO-252-3); Manufacturer: Texas Instruments; SymbolCreator: a0411947; SizeX_mm: 10.1; SizeY_mm: 6.6; SizeZ_mm: 2.52; CompType: IC; U/M: EA; SizeArea_mm2: 66.66; SizeAreaWB_mm2: 104.06

## Sheet TIDA-01414_Analog-Input_DaughterCard.SchDoc: Analog Connector Board
size 647 x 419 mm; Date: Not shown in title block; ApprovedBy: Not shown in title block; CheckedBy: Not shown in title block; Author: Not shown in title block; CompanyName: Not shown in title block; DrawnBy: LDN; Engineer: Not shown in title block; Organization: Not shown in title block; Address1: Not shown in title block; Address2: Not shown in title block; Address3: Not shown in title block; Address4: Not shown in title block; DocumentNumber: 10; Revision: Use project parameter SCH_Rev; SheetNumber: 10; SheetTotal: 12; PageSetup: Record=PageOptions¦CenterHorizontal=True¦CenterVertical=True¦PrintScale=1.00¦XCorrection=1.00¦YCorrection=1.00¦PrintKind=0¦BorderSize=5000000¦LeftOffset=0¦BottomOffset=0¦Orientation=2¦PaperLength=1000¦PaperWidth=1000¦Scale=100¦PaperSource=15¦PrintQuality=600¦MediaType=1¦DitherType=10¦PaperKind=Letter¦PrintScaleMode=1
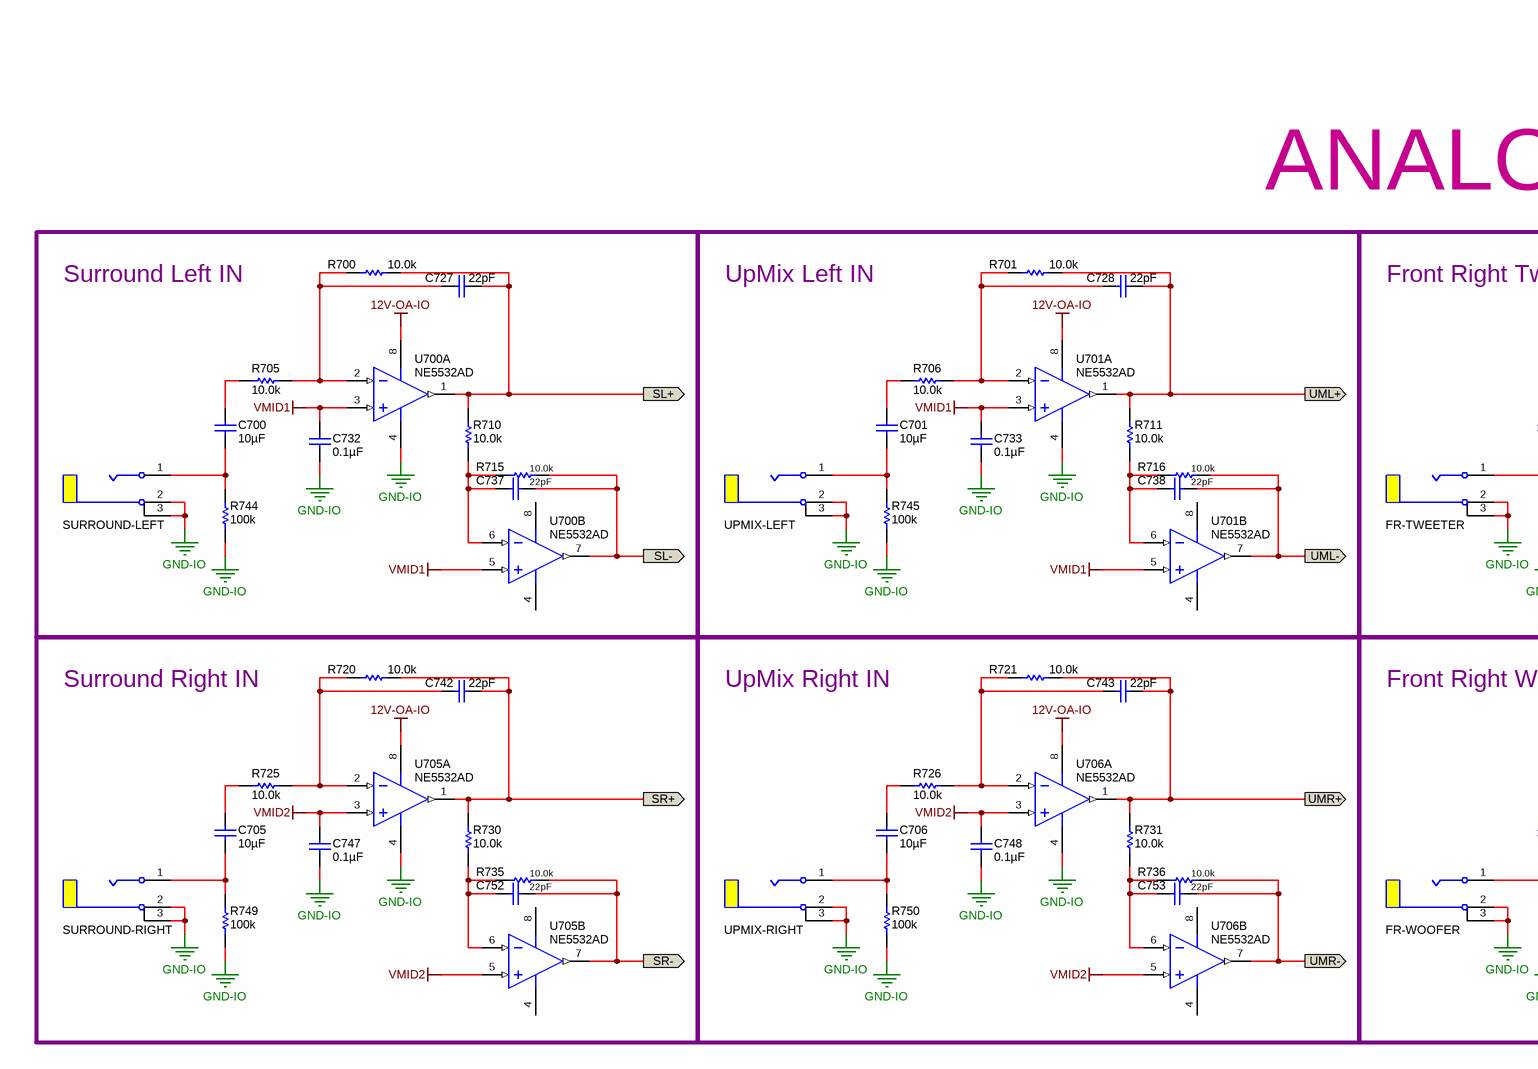
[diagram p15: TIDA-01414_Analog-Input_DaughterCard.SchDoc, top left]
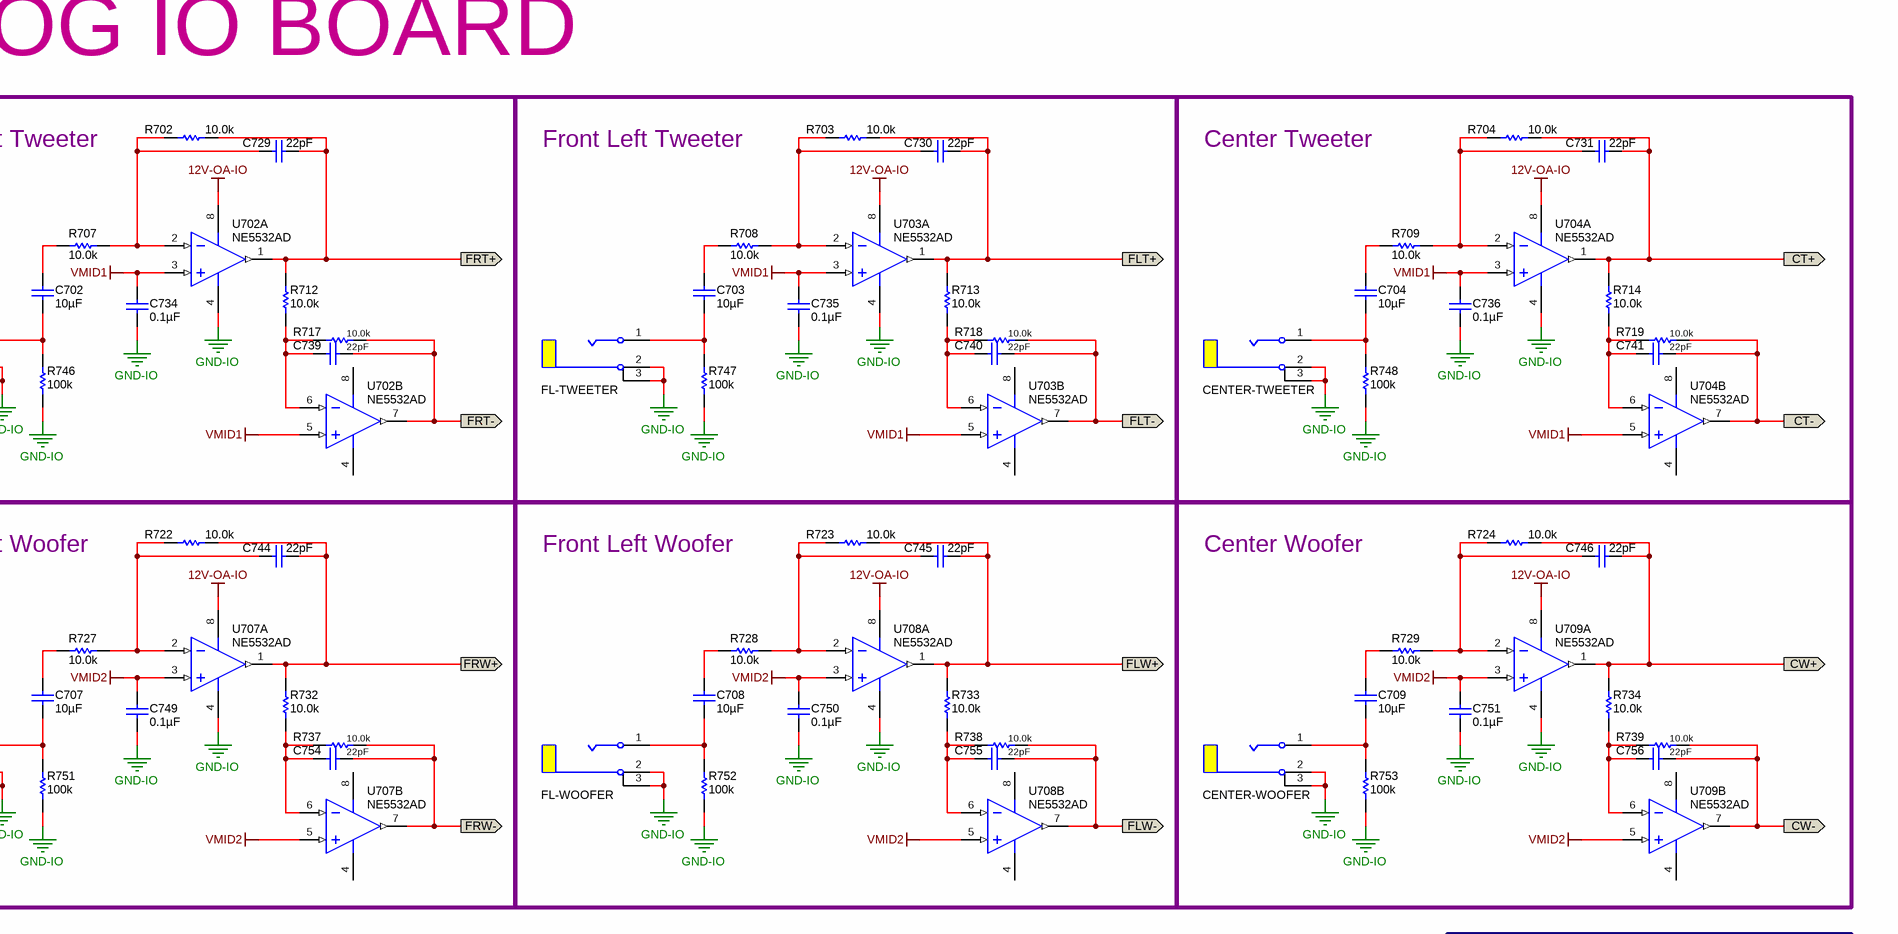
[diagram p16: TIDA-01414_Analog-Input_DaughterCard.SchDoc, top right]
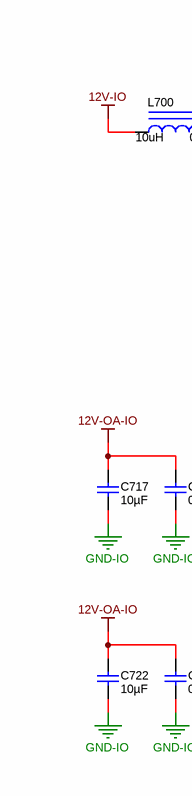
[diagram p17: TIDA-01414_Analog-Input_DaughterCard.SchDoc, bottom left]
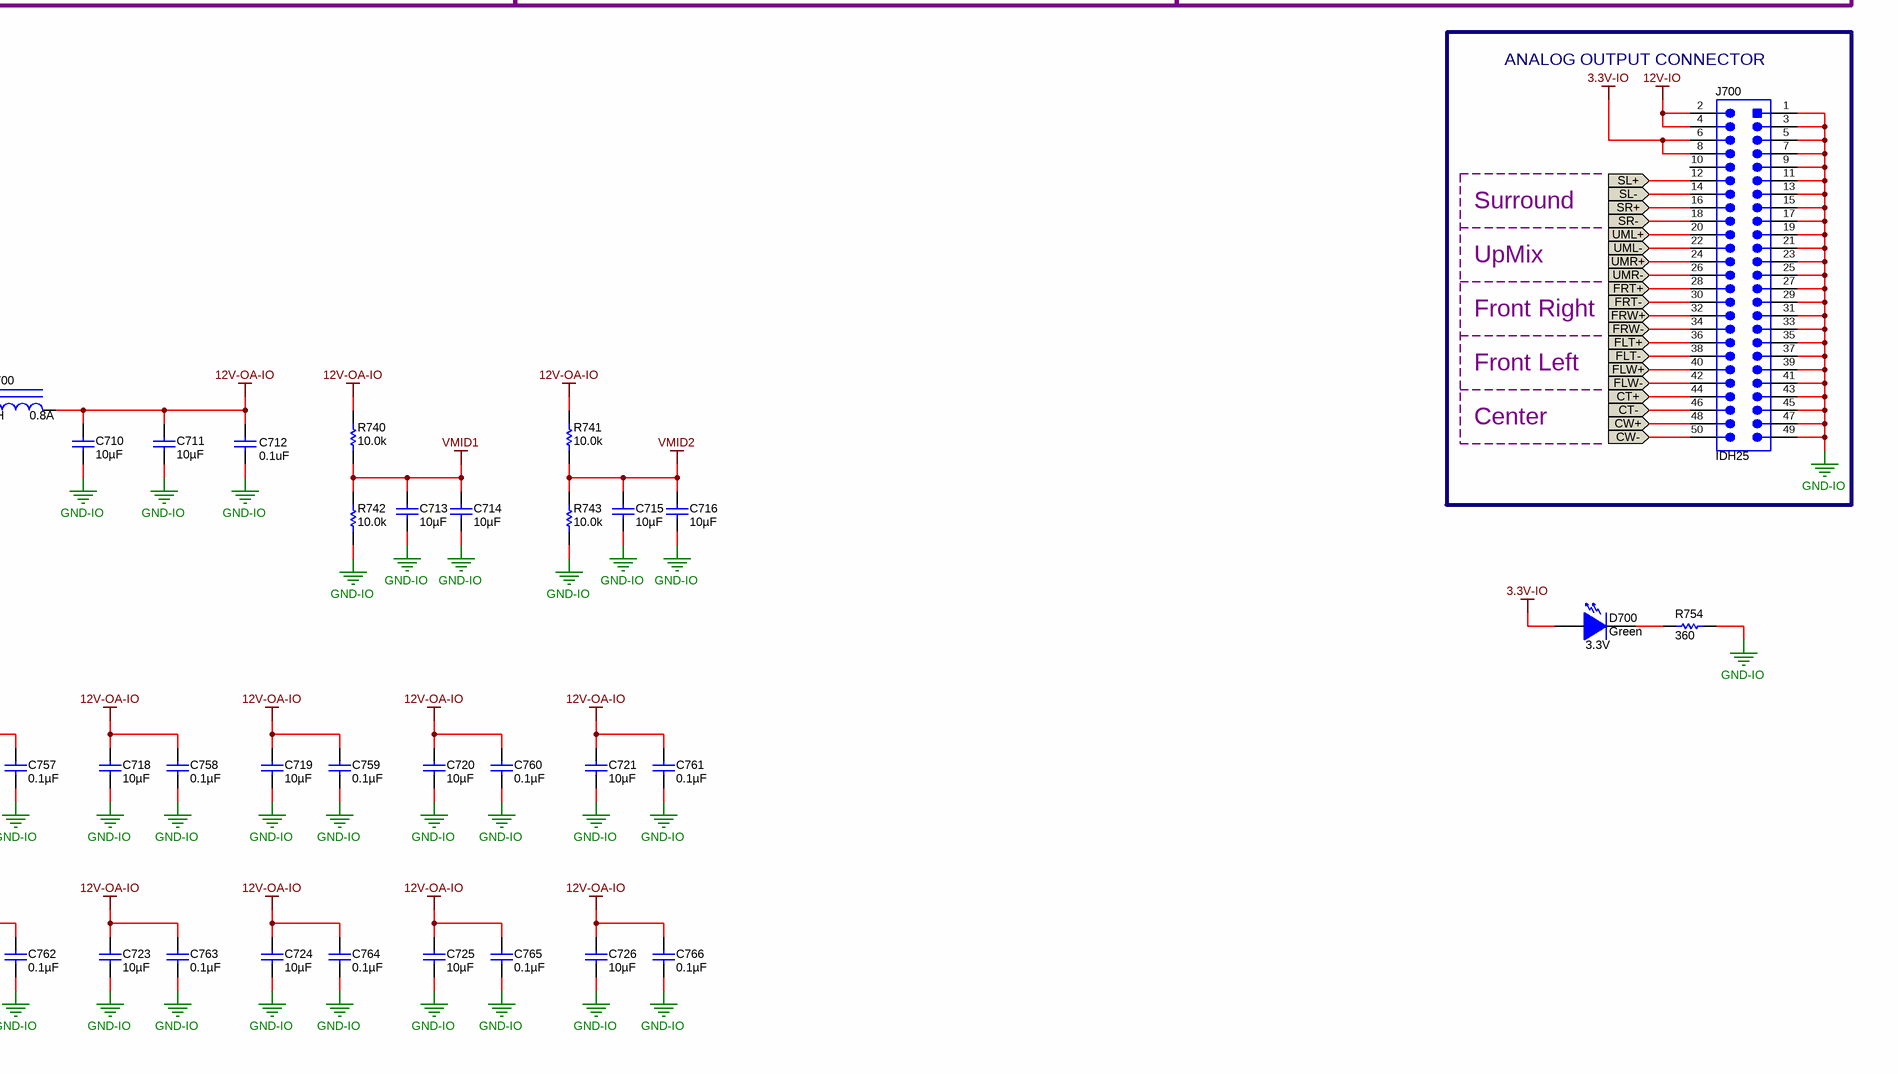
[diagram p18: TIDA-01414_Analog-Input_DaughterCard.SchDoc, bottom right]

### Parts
C700  ValueDisplayed: 10µF  [1206_180]  (hidden comment: GRM31CR71C106KAC7L)
C701  ValueDisplayed: 10µF  [1206_180]  (hidden comment: GRM31CR71C106KAC7L)
C702  ValueDisplayed: 10µF  [1206_180]  (hidden comment: GRM31CR71C106KAC7L)
C703  ValueDisplayed: 10µF  [1206_180]  (hidden comment: GRM31CR71C106KAC7L)
C704  ValueDisplayed: 10µF  [1206_180]  (hidden comment: GRM31CR71C106KAC7L)
C705  ValueDisplayed: 10µF  [1206_180]  (hidden comment: GRM31CR71C106KAC7L)
C706  ValueDisplayed: 10µF  [1206_180]  (hidden comment: GRM31CR71C106KAC7L)
C707  ValueDisplayed: 10µF  [1206_180]  (hidden comment: GRM31CR71C106KAC7L)
C708  ValueDisplayed: 10µF  [1206_180]  (hidden comment: GRM31CR71C106KAC7L)
C709  ValueDisplayed: 10µF  [1206_180]  (hidden comment: GRM31CR71C106KAC7L)
C710  ValueDisplayed: 10µF  [0805_KTR]  (hidden comment: EMK212BJ106KG-T)
C711  ValueDisplayed: 10µF  [0805_KTR]  (hidden comment: EMK212BJ106KG-T)
C712  value 0.1uF  [0603L]  (hidden comment: C0603C104K5RACTU)
C713  ValueDisplayed: 10µF  [0603L]  (hidden comment: GRM188R61C106MAALD)
C714  ValueDisplayed: 10µF  [0603L]  (hidden comment: GRM188R61C106MAALD)
C715  ValueDisplayed: 10µF  [0603L]  (hidden comment: GRM188R61C106MAALD)
C716  ValueDisplayed: 10µF  [0603L]  (hidden comment: GRM188R61C106MAALD)
C717  ValueDisplayed: 10µF  [0603L]  (hidden comment: GRM188R61C106MAALD)
C718  ValueDisplayed: 10µF  [0603L]  (hidden comment: GRM188R61C106MAALD)
C719  ValueDisplayed: 10µF  [0603L]  (hidden comment: GRM188R61C106MAALD)
C720  ValueDisplayed: 10µF  [0603L]  (hidden comment: GRM188R61C106MAALD)
C721  ValueDisplayed: 10µF  [0603L]  (hidden comment: GRM188R61C106MAALD)
C722  ValueDisplayed: 10µF  [0603L]  (hidden comment: GRM188R61C106MAALD)
C723  ValueDisplayed: 10µF  [0603L]  (hidden comment: GRM188R61C106MAALD)
C724  ValueDisplayed: 10µF  [0603L]  (hidden comment: GRM188R61C106MAALD)
C725  ValueDisplayed: 10µF  [0603L]  (hidden comment: GRM188R61C106MAALD)
C726  ValueDisplayed: 10µF  [0603L]  (hidden comment: GRM188R61C106MAALD)
C727  ValueDisplayed: 22pF  [0603L]  (hidden comment: GRM1885C1H220JA01D)
C728  ValueDisplayed: 22pF  [0603L]  (hidden comment: GRM1885C1H220JA01D)
C729  ValueDisplayed: 22pF  [0603L]  (hidden comment: GRM1885C1H220JA01D)
C730  ValueDisplayed: 22pF  [0603L]  (hidden comment: GRM1885C1H220JA01D)
C731  ValueDisplayed: 22pF  [0603L]  (hidden comment: GRM1885C1H220JA01D)
C732  ValueDisplayed: 0.1µF  [0402L]  (hidden comment: GRM155R71A104KA01D)
C733  ValueDisplayed: 0.1µF  [0402L]  (hidden comment: GRM155R71A104KA01D)
C734  ValueDisplayed: 0.1µF  [0402L]  (hidden comment: GRM155R71A104KA01D)
C735  ValueDisplayed: 0.1µF  [0402L]  (hidden comment: GRM155R71A104KA01D)
C736  ValueDisplayed: 0.1µF  [0402L]  (hidden comment: GRM155R71A104KA01D)
C737  ValueDisplayed: 22pF  [0603L]  (hidden comment: GRM1885C1H220JA01D)
C738  ValueDisplayed: 22pF  [0603L]  (hidden comment: GRM1885C1H220JA01D)
C739  ValueDisplayed: 22pF  [0603L]  (hidden comment: GRM1885C1H220JA01D)
C740  ValueDisplayed: 22pF  [0603L]  (hidden comment: GRM1885C1H220JA01D)
C741  ValueDisplayed: 22pF  [0603L]  (hidden comment: GRM1885C1H220JA01D)
C742  ValueDisplayed: 22pF  [0603L]  (hidden comment: GRM1885C1H220JA01D)
C743  ValueDisplayed: 22pF  [0603L]  (hidden comment: GRM1885C1H220JA01D)
C744  ValueDisplayed: 22pF  [0603L]  (hidden comment: GRM1885C1H220JA01D)
C745  ValueDisplayed: 22pF  [0603L]  (hidden comment: GRM1885C1H220JA01D)
C746  ValueDisplayed: 22pF  [0603L]  (hidden comment: GRM1885C1H220JA01D)
C747  ValueDisplayed: 0.1µF  [0402L]  (hidden comment: GRM155R71A104KA01D)
C748  ValueDisplayed: 0.1µF  [0402L]  (hidden comment: GRM155R71A104KA01D)
C749  ValueDisplayed: 0.1µF  [0402L]  (hidden comment: GRM155R71A104KA01D)
C750  ValueDisplayed: 0.1µF  [0402L]  (hidden comment: GRM155R71A104KA01D)
C751  ValueDisplayed: 0.1µF  [0402L]  (hidden comment: GRM155R71A104KA01D)
C752  ValueDisplayed: 22pF  [0603L]  (hidden comment: GRM1885C1H220JA01D)
C753  ValueDisplayed: 22pF  [0603L]  (hidden comment: GRM1885C1H220JA01D)
C754  ValueDisplayed: 22pF  [0603L]  (hidden comment: GRM1885C1H220JA01D)
C755  ValueDisplayed: 22pF  [0603L]  (hidden comment: GRM1885C1H220JA01D)
C756  ValueDisplayed: 22pF  [0603L]  (hidden comment: GRM1885C1H220JA01D)
C757  ValueDisplayed: 0.1µF  [0402L]  (hidden comment: GRM155R71A104KA01D)
C758  ValueDisplayed: 0.1µF  [0402L]  (hidden comment: GRM155R71A104KA01D)
C759  ValueDisplayed: 0.1µF  [0402L]  (hidden comment: GRM155R71A104KA01D)
C760  ValueDisplayed: 0.1µF  [0402L]  (hidden comment: GRM155R71A104KA01D)
C761  ValueDisplayed: 0.1µF  [0402L]  (hidden comment: GRM155R71A104KA01D)
C762  ValueDisplayed: 0.1µF  [0402L]  (hidden comment: GRM155R71A104KA01D)
C763  ValueDisplayed: 0.1µF  [0402L]  (hidden comment: GRM155R71A104KA01D)
C764  ValueDisplayed: 0.1µF  [0402L]  (hidden comment: GRM155R71A104KA01D)
C765  ValueDisplayed: 0.1µF  [0402L]  (hidden comment: GRM155R71A104KA01D)
C766  ValueDisplayed: 0.1µF  [0402L]  (hidden comment: GRM155R71A104KA01D)
CENTER-TWEETER  RCJ-024  [CONN_RCJ-024]  (value not drawn)
CENTER-WOOFER  RCJ-024  [CONN_RCJ-024]  (value not drawn)
D700  3.3V  value Green  [LED_LTST-C171]
FL-TWEETER  RCJ-024  [CONN_RCJ-024]  (value not drawn)
FL-WOOFER  RCJ-024  [CONN_RCJ-024]  (value not drawn)
FR-TWEETER  RCJ-024  [CONN_RCJ-024]  (value not drawn)
FR-WOOFER  RCJ-024  [CONN_RCJ-024]  (value not drawn)
J700  IDH25  [3M_N2550-6002-RB]
L700  value 10uH  Value2: 0.8A  [NRS4012]  (hidden comment: NRS4012T100MDGJV)
R700  ValueDisplayed: 10.0k  [0402L]  (hidden comment: ERJ-2RKF1002X)
R701  ValueDisplayed: 10.0k  [0402L]  (hidden comment: ERJ-2RKF1002X)
R702  ValueDisplayed: 10.0k  [0402L]  (hidden comment: ERJ-2RKF1002X)
R703  ValueDisplayed: 10.0k  [0402L]  (hidden comment: ERJ-2RKF1002X)
R704  ValueDisplayed: 10.0k  [0402L]  (hidden comment: ERJ-2RKF1002X)
R705  ValueDisplayed: 10.0k  [0402L]  (hidden comment: ERJ-2RKF1002X)
R706  ValueDisplayed: 10.0k  [0402L]  (hidden comment: ERJ-2RKF1002X)
R707  ValueDisplayed: 10.0k  [0402L]  (hidden comment: ERJ-2RKF1002X)
R708  ValueDisplayed: 10.0k  [0402L]  (hidden comment: ERJ-2RKF1002X)
R709  ValueDisplayed: 10.0k  [0402L]  (hidden comment: ERJ-2RKF1002X)
R710  ValueDisplayed: 10.0k  [0402L]  (hidden comment: ERJ-2RKF1002X)
R711  ValueDisplayed: 10.0k  [0402L]  (hidden comment: ERJ-2RKF1002X)
R712  ValueDisplayed: 10.0k  [0402L]  (hidden comment: ERJ-2RKF1002X)
R713  ValueDisplayed: 10.0k  [0402L]  (hidden comment: ERJ-2RKF1002X)
R714  ValueDisplayed: 10.0k  [0402L]  (hidden comment: ERJ-2RKF1002X)
R715  ValueDisplayed: 10.0k  [0402L]  (hidden comment: ERJ-2RKF1002X)
R716  ValueDisplayed: 10.0k  [0402L]  (hidden comment: ERJ-2RKF1002X)
R717  ValueDisplayed: 10.0k  [0402L]  (hidden comment: ERJ-2RKF1002X)
R718  ValueDisplayed: 10.0k  [0402L]  (hidden comment: ERJ-2RKF1002X)
R719  ValueDisplayed: 10.0k  [0402L]  (hidden comment: ERJ-2RKF1002X)
R720  ValueDisplayed: 10.0k  [0402L]  (hidden comment: ERJ-2RKF1002X)
R721  ValueDisplayed: 10.0k  [0402L]  (hidden comment: ERJ-2RKF1002X)
R722  ValueDisplayed: 10.0k  [0402L]  (hidden comment: ERJ-2RKF1002X)
R723  ValueDisplayed: 10.0k  [0402L]  (hidden comment: ERJ-2RKF1002X)
R724  ValueDisplayed: 10.0k  [0402L]  (hidden comment: ERJ-2RKF1002X)
R725  ValueDisplayed: 10.0k  [0402L]  (hidden comment: ERJ-2RKF1002X)
R726  ValueDisplayed: 10.0k  [0402L]  (hidden comment: ERJ-2RKF1002X)
R727  ValueDisplayed: 10.0k  [0402L]  (hidden comment: ERJ-2RKF1002X)
R728  ValueDisplayed: 10.0k  [0402L]  (hidden comment: ERJ-2RKF1002X)
R729  ValueDisplayed: 10.0k  [0402L]  (hidden comment: ERJ-2RKF1002X)
R730  ValueDisplayed: 10.0k  [0402L]  (hidden comment: ERJ-2RKF1002X)
R731  ValueDisplayed: 10.0k  [0402L]  (hidden comment: ERJ-2RKF1002X)
R732  ValueDisplayed: 10.0k  [0402L]  (hidden comment: ERJ-2RKF1002X)
R733  ValueDisplayed: 10.0k  [0402L]  (hidden comment: ERJ-2RKF1002X)
R734  ValueDisplayed: 10.0k  [0402L]  (hidden comment: ERJ-2RKF1002X)
R735  ValueDisplayed: 10.0k  [0402L]  (hidden comment: ERJ-2RKF1002X)
R736  ValueDisplayed: 10.0k  [0402L]  (hidden comment: ERJ-2RKF1002X)
R737  ValueDisplayed: 10.0k  [0402L]  (hidden comment: ERJ-2RKF1002X)
R738  ValueDisplayed: 10.0k  [0402L]  (hidden comment: ERJ-2RKF1002X)
R739  ValueDisplayed: 10.0k  [0402L]  (hidden comment: ERJ-2RKF1002X)
R740  ValueDisplayed: 10.0k  [0402L]  (hidden comment: ERJ-2RKF1002X)
R741  ValueDisplayed: 10.0k  [0402L]  (hidden comment: ERJ-2RKF1002X)
R742  ValueDisplayed: 10.0k  [0402L]  (hidden comment: ERJ-2RKF1002X)
R743  ValueDisplayed: 10.0k  [0402L]  (hidden comment: ERJ-2RKF1002X)
R744  value 100k  [0402L]  (hidden comment: CRCW0402100KFKED)
R745  value 100k  [0402L]  (hidden comment: CRCW0402100KFKED)
R746  value 100k  [0402L]  (hidden comment: CRCW0402100KFKED)
R747  value 100k  [0402L]  (hidden comment: CRCW0402100KFKED)
R748  value 100k  [0402L]  (hidden comment: CRCW0402100KFKED)
R749  value 100k  [0402L]  (hidden comment: CRCW0402100KFKED)
R750  value 100k  [0402L]  (hidden comment: CRCW0402100KFKED)
R751  value 100k  [0402L]  (hidden comment: CRCW0402100KFKED)
R752  value 100k  [0402L]  (hidden comment: CRCW0402100KFKED)
R753  value 100k  [0402L]  (hidden comment: CRCW0402100KFKED)
R754  value 360  [0402L]  (hidden comment: CRCW0402360RJNED)
SURROUND-LEFT  RCJ-024  [CONN_RCJ-024]  (value not drawn)
SURROUND-RIGHT  RCJ-024  [CONN_RCJ-024]  (value not drawn)
U700  NE5532AD  [D0008A_N]  (parts A,B of 2)
U701  NE5532AD  [D0008A_N]  (parts A,B of 2)
U702  NE5532AD  [D0008A_N]  (parts A,B of 2)
U703  NE5532AD  [D0008A_N]  (parts A,B of 2)
U704  NE5532AD  [D0008A_N]  (parts A,B of 2)
U705  NE5532AD  [D0008A_N]  (parts A,B of 2)
U706  NE5532AD  [D0008A_N]  (parts A,B of 2)
U707  NE5532AD  [D0008A_N]  (parts A,B of 2)
U708  NE5532AD  [D0008A_N]  (parts A,B of 2)
U709  NE5532AD  [D0008A_N]  (parts A,B of 2)
UPMIX-LEFT  RCJ-024  [CONN_RCJ-024]  (value not drawn)
UPMIX-RIGHT  RCJ-024  [CONN_RCJ-024]  (value not drawn)

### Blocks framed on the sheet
Surround Left IN: C700 C727 C732 C737 R700 R705 R710 R715 R744 SURROUND-LEFT U700
UpMix Left IN: C701 C728 C733 C738 R701 R706 R711 R716 R745 U701 UPMIX-LEFT
Front Right Tweeter: C702 C729 C734 C739 FR-TWEETER R702 R707 R712 R717 R746 U702
Front Left Tweeter: C703 C730 C735 C740 FL-TWEETER R703 R708 R713 R718 R747 U703
Center Tweeter: C704 C731 C736 C741 CENTER-TWEETER R704 R709 R714 R719 R748 U704
Surround Right IN: C705 C742 C747 C752 R720 R725 R730 R735 R749 SURROUND-RIGHT U705
UpMix Right IN: C706 C743 C748 C753 R721 R726 R731 R736 R750 U706 UPMIX-RIGHT
Front Right Woofer: C707 C744 C749 C754 FR-WOOFER R722 R727 R732 R737 R751 U707
Front Left Woofer: C708 C745 C750 C755 FL-WOOFER R723 R728 R733 R738 R752 U708
Center Woofer: C709 C746 C751 C756 CENTER-WOOFER R724 R729 R734 R739 R753 U709

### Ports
CT+ (in), CT+ (out), CT- (in), CT- (out), CW+ (in), CW+ (out), CW- (in), CW- (out), FLT+ (in), FLT+ (out), FLT- (in), FLT- (out), FLW+ (in), FLW+ (out), FLW- (in), FLW- (out), FRT+ (in), FRT+ (out), FRT- (in), FRT- (out), FRW+ (in), FRW+ (out), FRW- (in), FRW- (out), SL+ (in), SL+ (out), SL- (in), SL- (out), SR+ (in), SR+ (out), SR- (in), SR- (out), UML+ (in), UML+ (out), UML- (in), UML- (out), UMR+ (in), UMR+ (out), UMR- (in), UMR- (out)

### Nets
3.3V-IO: D700.1(A) J700.6 J700.8
12V-IO: J700.2 J700.4 L700.1
12V-OA-IO: C710.1 C711.1 C712.1 C717.2 C718.2 C719.2 C720.2 C721.2 C722.2 C723.2 C724.2 C725.2 C726.2 C757.2 C758.2 C759.2 C760.2 C761.2 C762.2 C763.2 C764.2 C765.2 C766.2 L700.2 R740.1 R741.1 U700.8(VCC+) U701.8(VCC+) U702.8(VCC+) U703.8(VCC+) U704.8(VCC+) U705.8(VCC+) U706.8(VCC+) U707.8(VCC+) U708.8(VCC+) U709.8(VCC+)
GND-IO: C710.2 C711.2 C712.2 C713.1 C714.1 C715.1 C716.1 C717.1 C718.1 C719.1 C720.1 C721.1 C722.1 C723.1 C724.1 C725.1 C726.1 C732.1 C733.1 C734.1 C735.1 C736.1 C747.1 C748.1 C749.1 C750.1 C751.1 C757.1 C758.1 C759.1 C760.1 C761.1 C762.1 C763.1 C764.1 C765.1 C766.1 CENTER-TWEETER.2 CENTER-TWEETER.3(R) CENTER-WOOFER.2 CENTER-WOOFER.3(R) FL-TWEETER.2 FL-TWEETER.3(R) FL-WOOFER.2 FL-WOOFER.3(R) FR-TWEETER.2 FR-TWEETER.3(R) FR-WOOFER.2 FR-WOOFER.3(R) J700.1 J700.3 J700.5 J700.7 J700.9 J700.11 J700.13 J700.15 J700.17 J700.19 J700.21 J700.23 J700.25 J700.27 J700.29 J700.31 J700.33 J700.35 J700.37 J700.39 J700.41 J700.43 J700.45 J700.47 J700.49 R742.2 R743.2 R744.1 R745.1 R746.1 R747.1 R748.1 R749.1 R750.1 R751.1 R752.1 R753.1 R754.2 SURROUND-LEFT.2 SURROUND-LEFT.3(R) SURROUND-RIGHT.2 SURROUND-RIGHT.3(R) U700.4(VCC-) U701.4(VCC-) U702.4(VCC-) U703.4(VCC-) U704.4(VCC-) U705.4(VCC-) U706.4(VCC-) U707.4(VCC-) U708.4(VCC-) U709.4(VCC-) UPMIX-LEFT.2 UPMIX-LEFT.3(R) UPMIX-RIGHT.2 UPMIX-RIGHT.3(R)
VMID1: C713.2 C714.2 C732.2 C733.2 C734.2 C735.2 C736.2 R740.2 R742.1 U700.3(IN1+) U700.5(IN2+) U701.3(IN1+) U701.5(IN2+) U702.3(IN1+) U702.5(IN2+) U703.3(IN1+) U703.5(IN2+) U704.3(IN1+) U704.5(IN2+)
VMID2: C715.2 C716.2 C747.2 C748.2 C749.2 C750.2 C751.2 R741.2 R743.1 U705.3(IN1+) U705.5(IN2+) U706.3(IN1+) U706.5(IN2+) U707.3(IN1+) U707.5(IN2+) U708.3(IN1+) U708.5(IN2+) U709.3(IN1+) U709.5(IN2+)
CT+: C731.2 J700.44 R704.1 R714.1 U704.1(OUT1) ; port CT+
CT-: C741.2 J700.46 R719.1 U704.7(OUT2) ; port CT-
CW+: C746.2 J700.48 R724.1 R734.1 U709.1(OUT1) ; port CW+
CW-: C756.2 J700.50 R739.1 U709.7(OUT2) ; port CW-
FLT+: C730.2 J700.36 R703.1 R713.1 U703.1(OUT1) ; port FLT+
FLT-: C740.2 J700.38 R718.1 U703.7(OUT2) ; port FLT-
FLW+: C745.2 J700.40 R723.1 R733.1 U708.1(OUT1) ; port FLW+
FLW-: C755.2 J700.42 R738.1 U708.7(OUT2) ; port FLW-
FRT+: C729.2 J700.28 R702.1 R712.1 U702.1(OUT1) ; port FRT+
FRT-: C739.2 J700.30 R717.1 U702.7(OUT2) ; port FRT-
FRW+: C744.2 J700.32 R722.1 R732.1 U707.1(OUT1) ; port FRW+
FRW-: C754.2 J700.34 R737.1 U707.7(OUT2) ; port FRW-
SL+: C727.2 J700.12 R700.1 R710.1 U700.1(OUT1) ; port SL+
SL-: C737.2 J700.14 R715.1 U700.7(OUT2) ; port SL-
SR+: C742.2 J700.16 R720.1 R730.1 U705.1(OUT1) ; port SR+
SR-: C752.2 J700.18 R735.1 U705.7(OUT2) ; port SR-
UML+: C728.2 J700.20 R701.1 R711.1 U701.1(OUT1) ; port UML+
UML-: C738.2 J700.22 R716.1 U701.7(OUT2) ; port UML-
UMR+: C743.2 J700.24 R721.1 R731.1 U706.1(OUT1) ; port UMR+
UMR-: C753.2 J700.26 R736.1 U706.7(OUT2) ; port UMR-
NetC700_1: C700.1 R744.2 SURROUND-LEFT.1
NetC700_2: C700.2 R705.2
NetC701_1: C701.1 R745.2 UPMIX-LEFT.1
NetC701_2: C701.2 R706.2
NetC702_1: C702.1 FR-TWEETER.1 R746.2
NetC702_2: C702.2 R707.2
NetC703_1: C703.1 FL-TWEETER.1 R747.2
NetC703_2: C703.2 R708.2
NetC704_1: C704.1 CENTER-TWEETER.1 R748.2
NetC704_2: C704.2 R709.2
NetC705_1: C705.1 R749.2 SURROUND-RIGHT.1
NetC705_2: C705.2 R725.2
NetC706_1: C706.1 R750.2 UPMIX-RIGHT.1
NetC706_2: C706.2 R726.2
NetC707_1: C707.1 FR-WOOFER.1 R751.2
NetC707_2: C707.2 R727.2
NetC708_1: C708.1 FL-WOOFER.1 R752.2
NetC708_2: C708.2 R728.2
NetC709_1: C709.1 CENTER-WOOFER.1 R753.2
NetC709_2: C709.2 R729.2
NetC727_1: C727.1 R700.2 R705.1 U700.2(IN1-)
NetC728_1: C728.1 R701.2 R706.1 U701.2(IN1-)
NetC729_1: C729.1 R702.2 R707.1 U702.2(IN1-)
NetC730_1: C730.1 R703.2 R708.1 U703.2(IN1-)
NetC731_1: C731.1 R704.2 R709.1 U704.2(IN1-)
NetC737_1: C737.1 R710.2 R715.2 U700.6(IN2-)
NetC738_1: C738.1 R711.2 R716.2 U701.6(IN2-)
NetC739_1: C739.1 R712.2 R717.2 U702.6(IN2-)
NetC740_1: C740.1 R713.2 R718.2 U703.6(IN2-)
NetC741_1: C741.1 R714.2 R719.2 U704.6(IN2-)
NetC742_1: C742.1 R720.2 R725.1 U705.2(IN1-)
NetC743_1: C743.1 R721.2 R726.1 U706.2(IN1-)
NetC744_1: C744.1 R722.2 R727.1 U707.2(IN1-)
NetC745_1: C745.1 R723.2 R728.1 U708.2(IN1-)
NetC746_1: C746.1 R724.2 R729.1 U709.2(IN1-)
NetC752_1: C752.1 R730.2 R735.2 U705.6(IN2-)
NetC753_1: C753.1 R731.2 R736.2 U706.6(IN2-)
NetC754_1: C754.1 R732.2 R737.2 U707.6(IN2-)
NetC755_1: C755.1 R733.2 R738.2 U708.6(IN2-)
NetC756_1: C756.1 R734.2 R739.2 U709.6(IN2-)
NetD700_2: D700.2(K) R754.1

Not connected (* = marked no-connect by the designer): J700 10

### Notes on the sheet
- ANALOG IO BOARD
- (near J700) ANALOG OUTPUT CONNECTOR
- Surround
- Front Right
- UpMix
- Front Left
- Center

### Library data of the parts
C700-C709 = GRM31CR71C106KAC7L: as C600 on sheet TIDA-01414_SubWooferChannel
C710 C711 = EMK212BJ106KG-T: as C617 on sheet TIDA-01414_SubWooferChannel
C712 = C0603C104K5RACTU: as C619 on sheet TIDA-01414_SubWooferChannel
C713-C726 = GRM188R61C106MAALD: as C608 on sheet TIDA-01414_SubWooferChannel
C727-C731 C737-C746 C752-C756 = GRM1885C1H220JA01D: as C2 on sheet TIDA-01414_SubWooferChannel
C732-C736 C747-C751 C757-C766 = GRM155R71A104KA01D: as C602 on sheet TIDA-01414_SubWooferChannel
CENTER-TWEETER CENTER-WOOFER FL-TWEETER FL-WOOFER FR-TWEETER FR-WOOFER SURROUND-LEFT SURROUND-RIGHT UPMIX-LEFT UPMIX-RIGHT = RCJ-024: as SUBOUT on sheet TIDA-01414_SubWooferChannel
D700 = LTST-C171GKT: as D13 on sheet TIDA-01414_PowerSupplies
J700 = N2550-6002-RB: Header(Shrouded), 2.54mm, 25x2, Gold, TH; Manufacturer: 3M; SymbolCreator: a0799628; Pitch_mm: 2.54; Gender: Male; Shrouded: Y; Row_Count: 2
L700 = NRS4012T100MDGJV: as L600 on sheet TIDA-01414_SubWooferChannel
R700-R743 = ERJ-2RKF1002X: as R600 on sheet TIDA-01414_SubWooferChannel
R744-R753 = CRCW0402100KFKED: as R1 on sheet TIDA-01414_SubWooferChannel
R754 = CRCW0402360RJNED: as R51 on sheet TIDA-01414_PowerSupplies
U700-U709 = NE5532AD: as U601 on sheet TIDA-01414_SubWooferChannel

## Sheet TIDA-01414_TID_Hardware.SchDoc: Hardware
size Letter; Date: Not shown in title block; ApprovedBy: Not shown in title block; CheckedBy: Not shown in title block; Author: Not shown in title block; CompanyName: Not shown in title block; DrawnBy: LDN; Engineer: Not shown in title block; Organization: Not shown in title block; Address1: Not shown in title block; Address2: Not shown in title block; Address3: Not shown in title block; Address4: Not shown in title block; DocumentNumber: 11; Revision: Use project parameter SCH_Rev; SheetNumber: 11; SheetTotal: 12; PageSetup: Record=PageOptions¦CenterHorizontal=True¦CenterVertical=True¦PrintScale=1.00¦XCorrection=1.00¦YCorrection=1.00¦PrintKind=0¦BorderSize=5000000¦LeftOffset=0¦BottomOffset=0¦Orientation=2¦PaperLength=1000¦PaperWidth=1000¦Scale=100¦PaperSource=15¦PrintQuality=600¦MediaType=1¦DitherType=10¦PaperKind=Letter¦PrintScaleMode=1
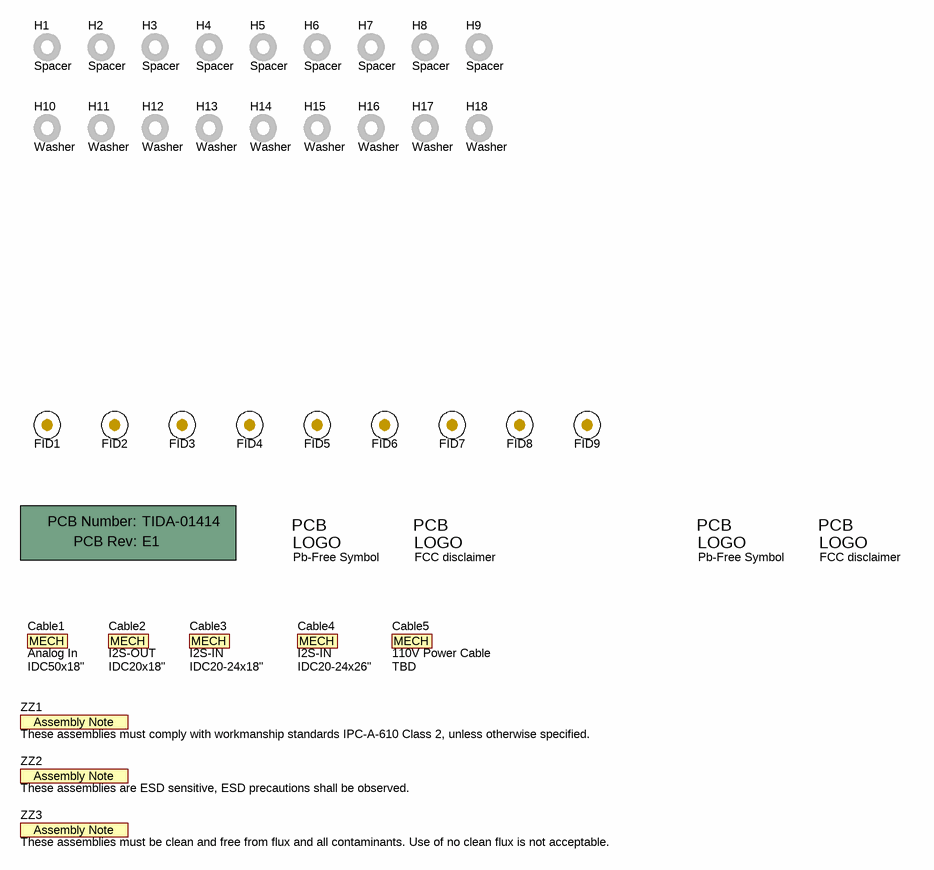
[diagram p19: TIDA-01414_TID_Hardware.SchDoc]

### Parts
!PCB1  Printed Circuit Board  (value not drawn)  (mechanical)
Cable1  Analog In  CableDescription: IDC50x18"
Cable2  I2S-OUT  PartNumber: IDC20x18"
Cable3  I2S-IN  PartNumber: IDC20-24x18"
Cable4  I2S-IN  PartNumber: IDC20-24x26"
Cable5  110V Power Cable  PartNumber: TBD
FID1  Fiducial  [Fiducial10-20]  (value not drawn)
FID2  Fiducial  [Fiducial10-20]  (value not drawn)
FID3  Fiducial  [Fiducial10-20]  (value not drawn)
FID4  Fiducial  [Fiducial10-20]  (value not drawn)
FID5  Fiducial  [Fiducial10-20]  (value not drawn)
FID6  Fiducial  [Fiducial10-20]  (value not drawn)
FID7  Fiducial  [Fiducial10-20]  (value not drawn)
FID8  Fiducial  [Fiducial10-20]  (value not drawn)
FID9  Fiducial  [Fiducial10-20]  (value not drawn)
H1  Spacer  [Bivar_9912-250]
H2  Spacer  [Bivar_9912-250]
H3  Spacer  [Bivar_9912-250]
H4  Spacer  [Bivar_9912-250]
H5  Spacer  [Bivar_9912-250]
H6  Spacer  [Bivar_9912-250]
H7  Spacer  [Bivar_9912-250]
H8  Spacer  [Bivar_9912-250]
H9  Spacer  [Bivar_9912-250]
H10  Washer  [Keystone_3205]
H11  Washer  [Keystone_3205]
H12  Washer  [Keystone_3205]
H13  Washer  [Keystone_3205]
H14  Washer  [Keystone_3205]
H15  Washer  [Keystone_3205]
H16  Washer  [Keystone_3205]
H17  Washer  [Keystone_3205]
H18  Washer  [Keystone_3205]
Logo2  Pb-Free Symbol  [Pb-Free_Overlay_Small]  (no BOM)
Logo3  FCC disclaimer  [FCC_disclaimer_stacked]  (no BOM)
Logo5  Pb-Free Symbol  [Pb-Free_Overlay_Small]  (no BOM)
Logo6  FCC disclaimer  [FCC_disclaimer_stacked]  (no BOM)
ZZ1  These assemblies must comply with workmanship standards IPC-A-610 Class 2, unless otherwise specified.  [AssemblyNote]  (no BOM)
ZZ2  These assemblies are ESD sensitive, ESD precautions shall be observed.  [AssemblyNote]  (no BOM)
ZZ3  These assemblies must be clean and free from flux and all contaminants. Use of no clean flux is not acceptable.  [AssemblyNote]  (no BOM)

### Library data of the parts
!PCB1 = PCB: Manufacturer: Any; PartNumber: TIDA-01414; SymbolCreator: a0412235
Cable1 = MechPart: 50 Pin Ribbon Cable Assembly, 18"; Manufacturer: Used in BOM report; PartNumber: H3CCS-5018G; SymbolCreator: codlsc; CompType: Mechanical; U/M: EA
Cable2 Cable5 = MechPart: 20 Pin Ribbon Cable Assembly, 18"; Manufacturer: Used in BOM report; SymbolCreator: codlsc; CompType: Mechanical; U/M: EA
Cable3 = MechPart: 18" 20-24 Pin Ribbon Cable Assembly; Manufacturer: Used in BOM report; SymbolCreator: codlsc; CompType: Mechanical; U/M: EA
Cable4 = MechPart: 26" 20-24 Pin Ribbon Cable Assembly; Manufacturer: Used in BOM report; SymbolCreator: codlsc; CompType: Mechanical; U/M: EA
FID1-FID9 = Fiducial: Fiducial mark.  There is nothing to buy or mount.; SymbolCreator: codlsc
H1-H9 = 9912-250: NYLON TUBE SPACER; Manufacturer: Bivar; CompType: Nylon Spacer
H10-H18 = 3205: Flat Nylon Washer; Manufacturer: Keystone; SymbolCreator: a0412235
Logo2 Logo5 = Pb-Free: SymbolCreator: a0412235
Logo3 Logo6 = FCC_disclaimer: SymbolCreator: codlsc
ZZ1-ZZ3 = AssemblyNote: SymbolCreator: codlsc

## Sheet TIDA-01414_CableAssemblies.SchDoc: Cable Assemblies
size 538 x 342 mm; Date: Not shown in title block; ApprovedBy: Not shown in title block; CheckedBy: Not shown in title block; Author: Not shown in title block; CompanyName: Not shown in title block; DrawnBy: LDN; Engineer: Not shown in title block; Organization: Not shown in title block; Address1: Not shown in title block; Address2: Not shown in title block; Address3: Not shown in title block; Address4: Not shown in title block; DocumentNumber: 12; Revision: Use project parameter SCH_Rev; SheetNumber: 12; SheetTotal: 12; PageSetup: Record=PageOptions¦CenterHorizontal=True¦CenterVertical=True¦PrintScale=1.00¦XCorrection=1.00¦YCorrection=1.00¦PrintKind=0¦BorderSize=5000000¦LeftOffset=0¦BottomOffset=0¦Orientation=2¦PaperLength=1000¦PaperWidth=1000¦Scale=100¦PaperSource=15¦PrintQuality=600¦MediaType=1¦DitherType=10¦PaperKind=Letter¦PrintScaleMode=1
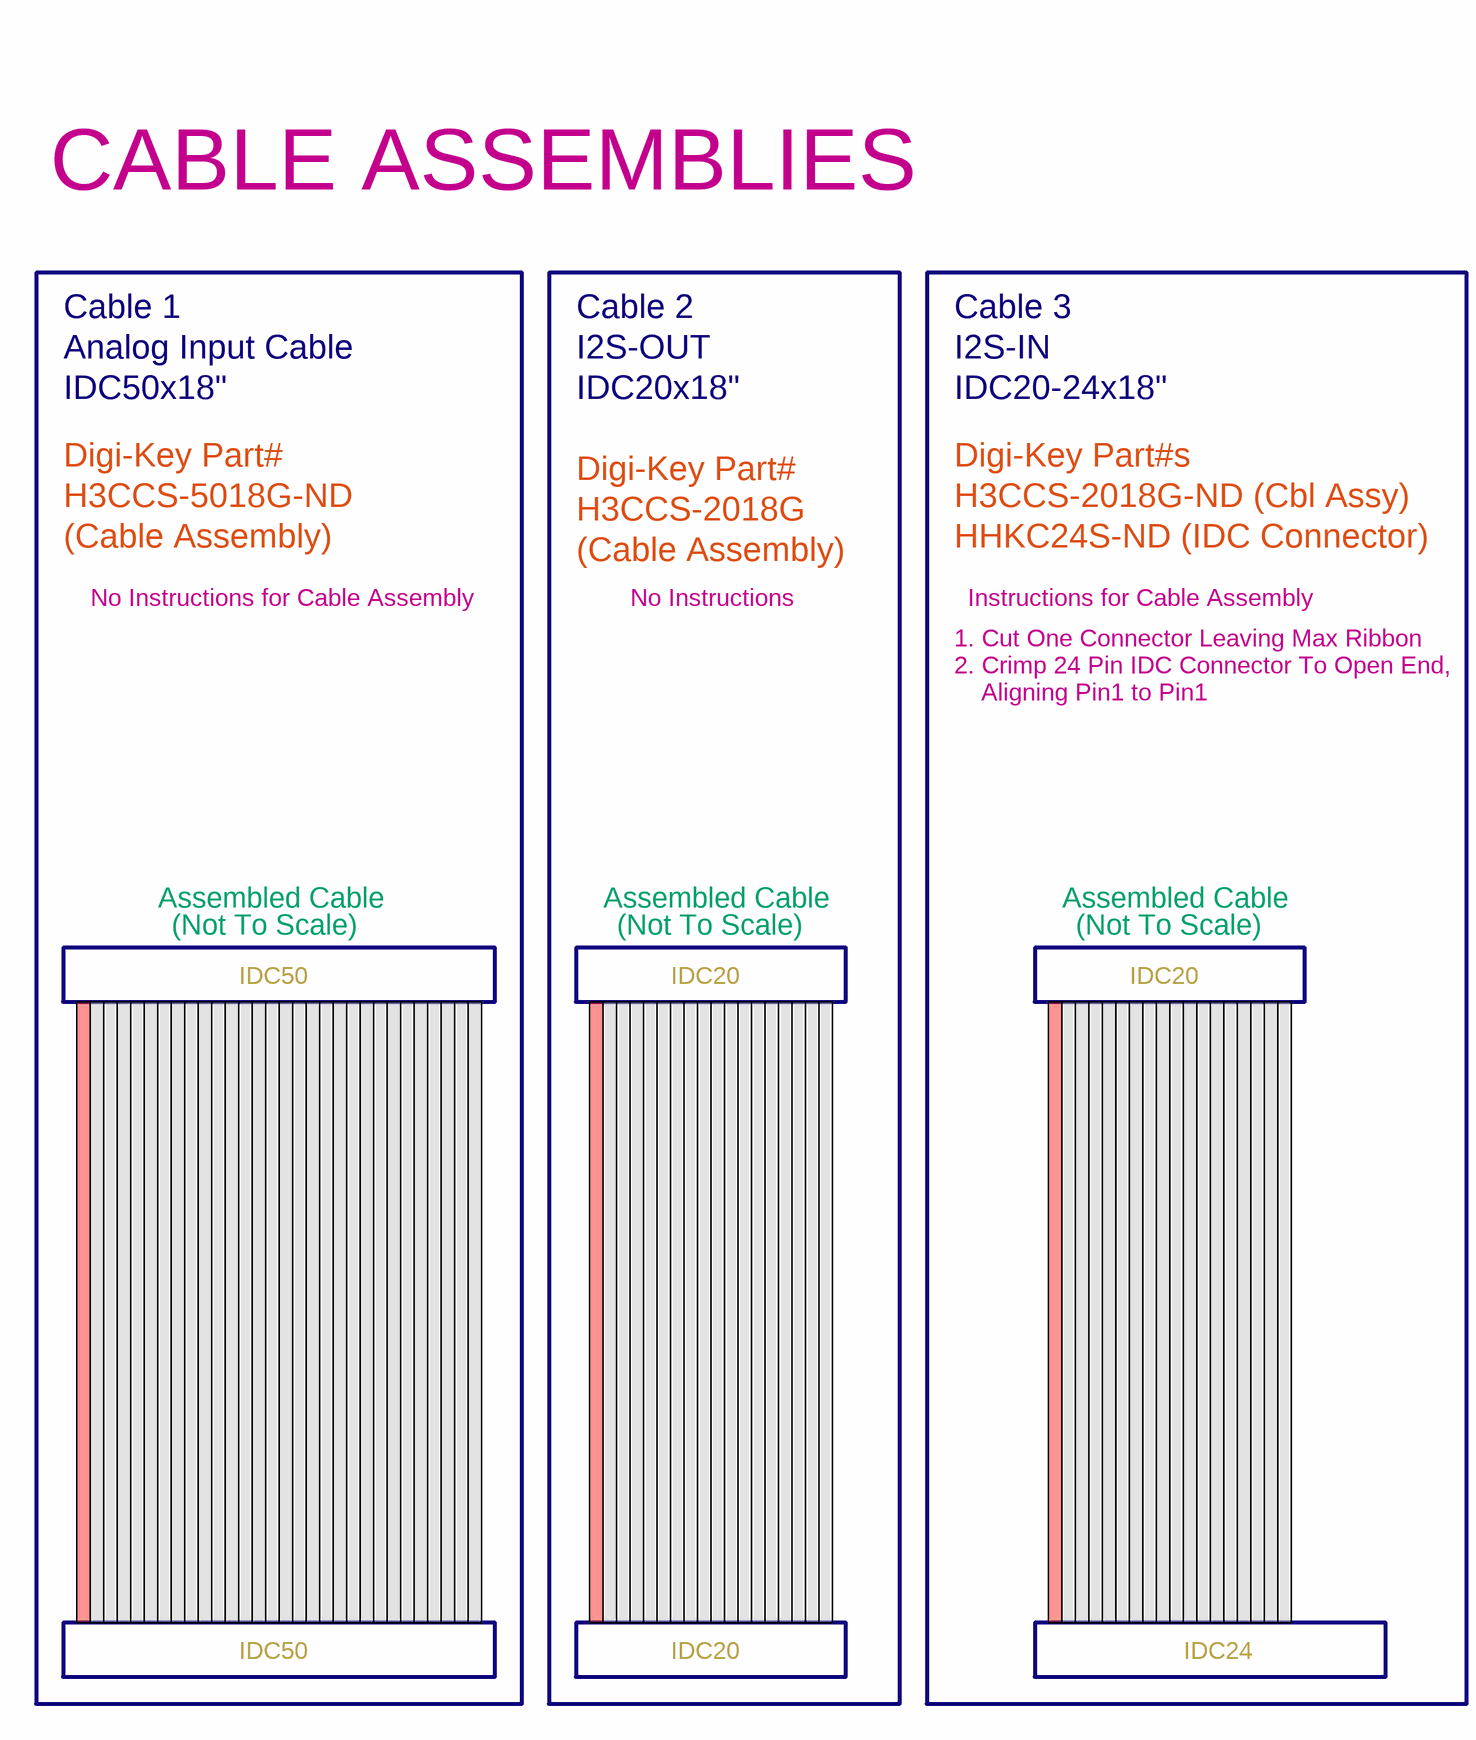
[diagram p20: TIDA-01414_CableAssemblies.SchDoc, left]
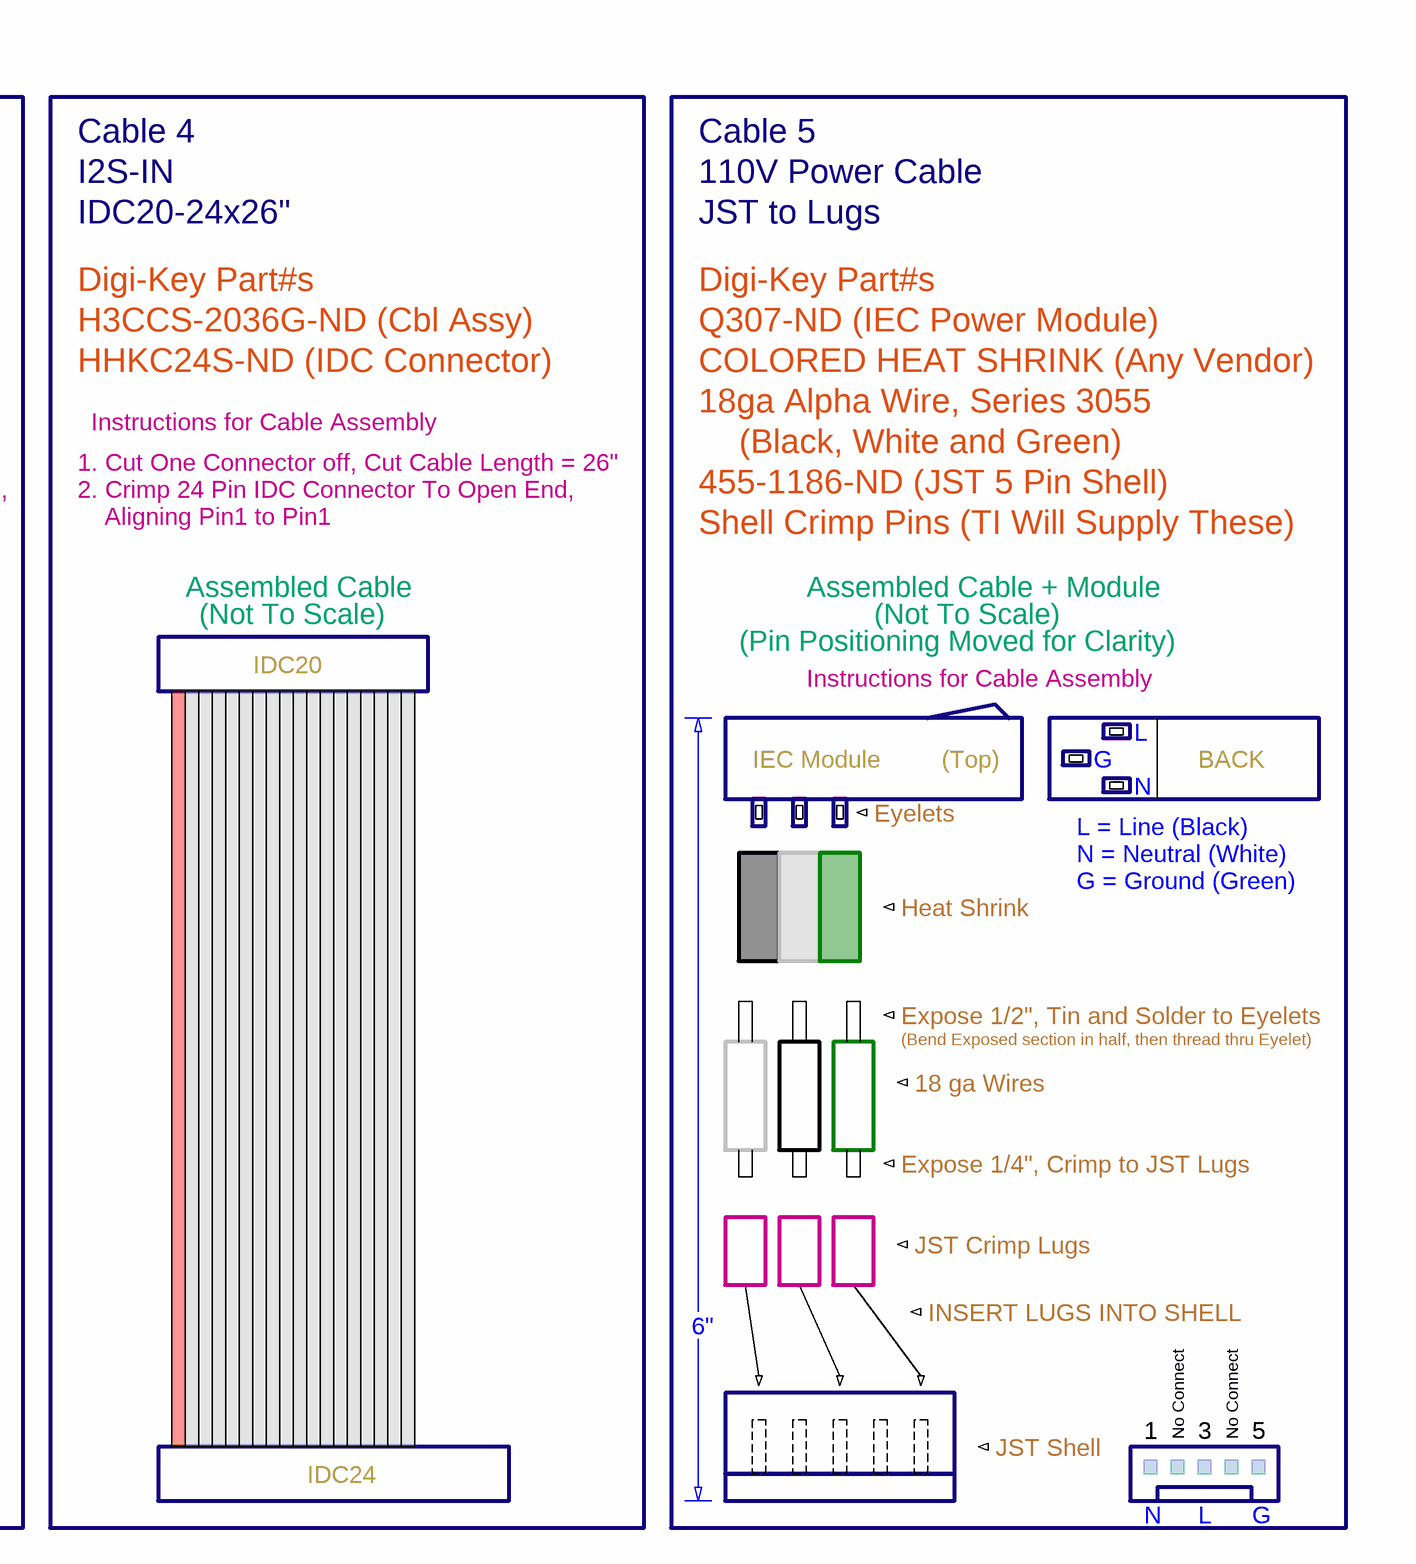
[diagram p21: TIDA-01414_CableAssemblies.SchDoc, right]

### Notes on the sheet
- CABLE ASSEMBLIES
- Cable 1
- Cable 2
- Cable 3
- Cable 4
- Cable 5
- Analog Input Cable
- IDC50x18"
- I2S-OUT
- IDC20x18"
- I2S-IN
- IDC20-24x18"
- IDC20-24x26"
- 110V Power Cable
- JST to Lugs
- Digi-Key Part#
- Digi-Key Part#s
- H3CCS-5018G-ND
- H3CCS-2018G
- H3CCS-2018G-ND (Cbl Assy)
- H3CCS-2036G-ND (Cbl Assy)
- Q307-ND (IEC Power Module)
- (Cable Assembly)
- HHKC24S-ND (IDC Connector)
- COLORED HEAT SHRINK (Any Vendor)
- 18ga Alpha Wire, Series 3055
- No Instructions for Cable Assembly
- No Instructions
- 1. Cut One Connector Leaving Max Ribbon
- Instructions for Cable Assembly
- 1. Cut One Connector off, Cut Cable Length = 26"
- 455-1186-ND (JST 5 Pin Shell)
- (Black, White and Green)
- 2. Crimp 24 Pin IDC Connector To Open End,
- Aligning Pin1 to Pin1
- Shell Crimp Pins (TI Will Supply These)
- Assembled Cable
- (Not To Scale)
- Assembled Cable + Module
- IDC20
- (Pin Positioning Moved for Clarity)
- L
- IDC50
- IEC Module
- Eyelets
- (Top)
- G
- N
- BACK
- L = Line (Black)
- N = Neutral (White)
- G = Ground (Green)
- Heat Shrink
- Expose 1/2", Tin and Solder to Eyelets
- (Bend Exposed section in half, then thread thru Eyelet)
- 18 ga Wires
- Expose 1/4", Crimp to JST Lugs
- JST Crimp Lugs
- 6"
- INSERT LUGS INTO SHELL
- IDC24
- JST Shell
- 1
- No Connect
- 3
- 5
